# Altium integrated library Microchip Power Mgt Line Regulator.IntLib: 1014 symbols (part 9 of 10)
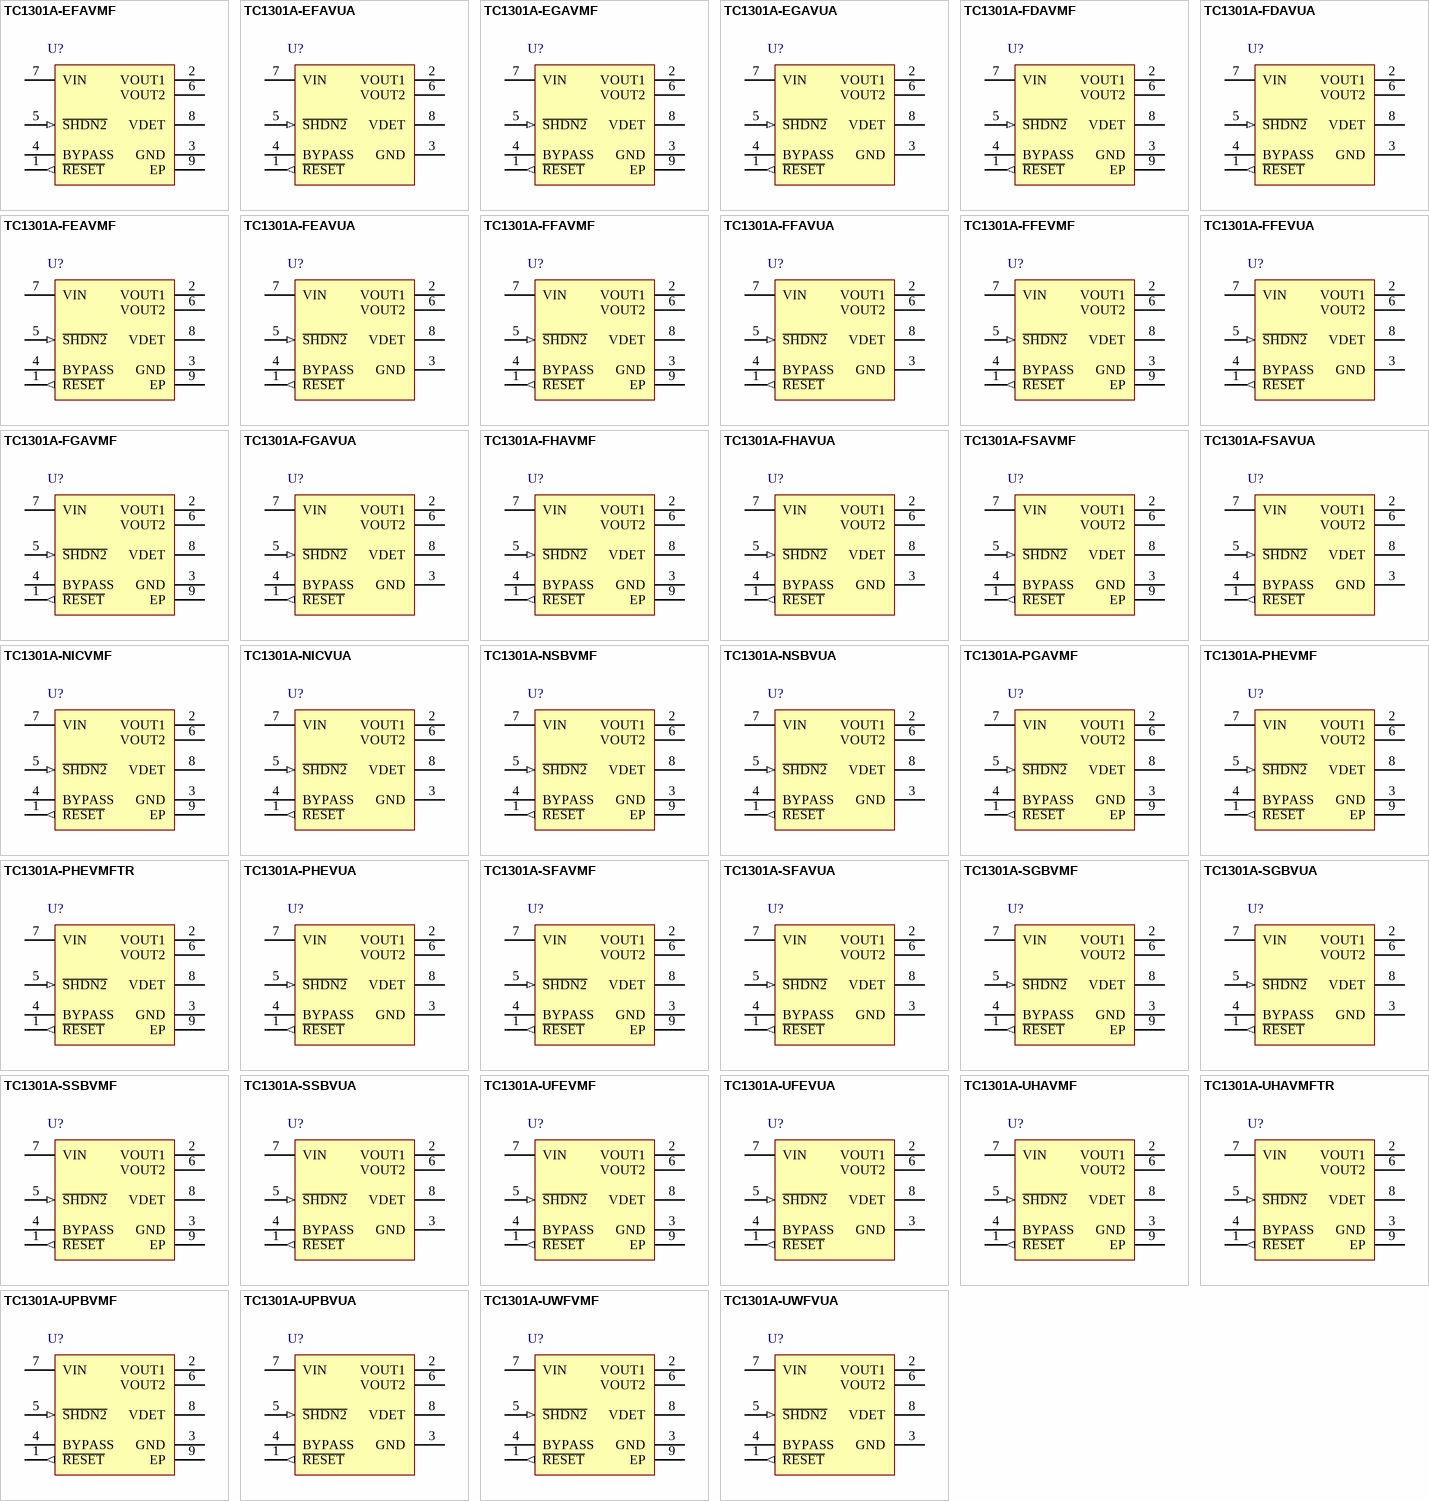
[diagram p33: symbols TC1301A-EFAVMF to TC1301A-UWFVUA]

## TC1301A-UHAVMFTR
designator U?
Dual LDO with Microcontroller Active-Low Reset Function, 8-Pin DFN, Extended Temperature, Tape and Reel
footprint DFN-MF8 (SON, 8-Leads, Body 3x3mm, Pitch 0.65mm, Microchip Recommended)
pins: 1 ~{RESET} (out), 2 VOUT1 (power), 3 GND (power), 4 BYPASS, 5 ~{SHDN2} (in), 6 VOUT2 (power), 7 VIN (power), 8 VDET (power), 9 EP (power)

## TC1301A-UPBVMF
designator U?
Dual LDO with Microcontroller Active-Low Reset Function, 8-Pin DFN, Extended Temperature
footprint DFN-MF8 (SON, 8-Leads, Body 3x3mm, Pitch 0.65mm, Microchip Recommended)
pins: 1 ~{RESET} (out), 2 VOUT1 (power), 3 GND (power), 4 BYPASS, 5 ~{SHDN2} (in), 6 VOUT2 (power), 7 VIN (power), 8 VDET (power), 9 EP (power)

## TC1301A-UPBVUA
designator U?
Dual LDO with Microcontroller Active-Low Reset Function, 8-Pin MSOP, Extended Temperature
footprint MSOP-UA8_N (TSOP, 8-Leads, Body 3x3mm, Pitch 0.65mm, IPC Medium Density)
footprint MSOP-UA8_L (TSOP, 8-Leads, Body 3x3mm, Pitch 0.65mm, IPC High Density)
footprint MSOP-UA8_M (TSOP, 8-Leads, Body 3x3mm, Pitch 0.65mm, IPC Low Density)
pins: 1 ~{RESET} (out), 2 VOUT1 (power), 3 GND (power), 4 BYPASS, 5 ~{SHDN2} (in), 6 VOUT2 (power), 7 VIN (power), 8 VDET (power)

## TC1301A-UWFVMF
designator U?
Dual LDO with Microcontroller Active-Low Reset Function, 8-Pin DFN, Extended Temperature
footprint DFN-MF8 (SON, 8-Leads, Body 3x3mm, Pitch 0.65mm, Microchip Recommended)
pins: 1 ~{RESET} (out), 2 VOUT1 (power), 3 GND (power), 4 BYPASS, 5 ~{SHDN2} (in), 6 VOUT2 (power), 7 VIN (power), 8 VDET (power), 9 EP (power)

## TC1301A-UWFVUA
designator U?
Dual LDO with Microcontroller Active-Low Reset Function, 8-Pin MSOP, Extended Temperature
footprint MSOP-UA8_N (TSOP, 8-Leads, Body 3x3mm, Pitch 0.65mm, IPC Medium Density)
footprint MSOP-UA8_L (TSOP, 8-Leads, Body 3x3mm, Pitch 0.65mm, IPC High Density)
footprint MSOP-UA8_M (TSOP, 8-Leads, Body 3x3mm, Pitch 0.65mm, IPC Low Density)
pins: 1 ~{RESET} (out), 2 VOUT1 (power), 3 GND (power), 4 BYPASS, 5 ~{SHDN2} (in), 6 VOUT2 (power), 7 VIN (power), 8 VDET (power)

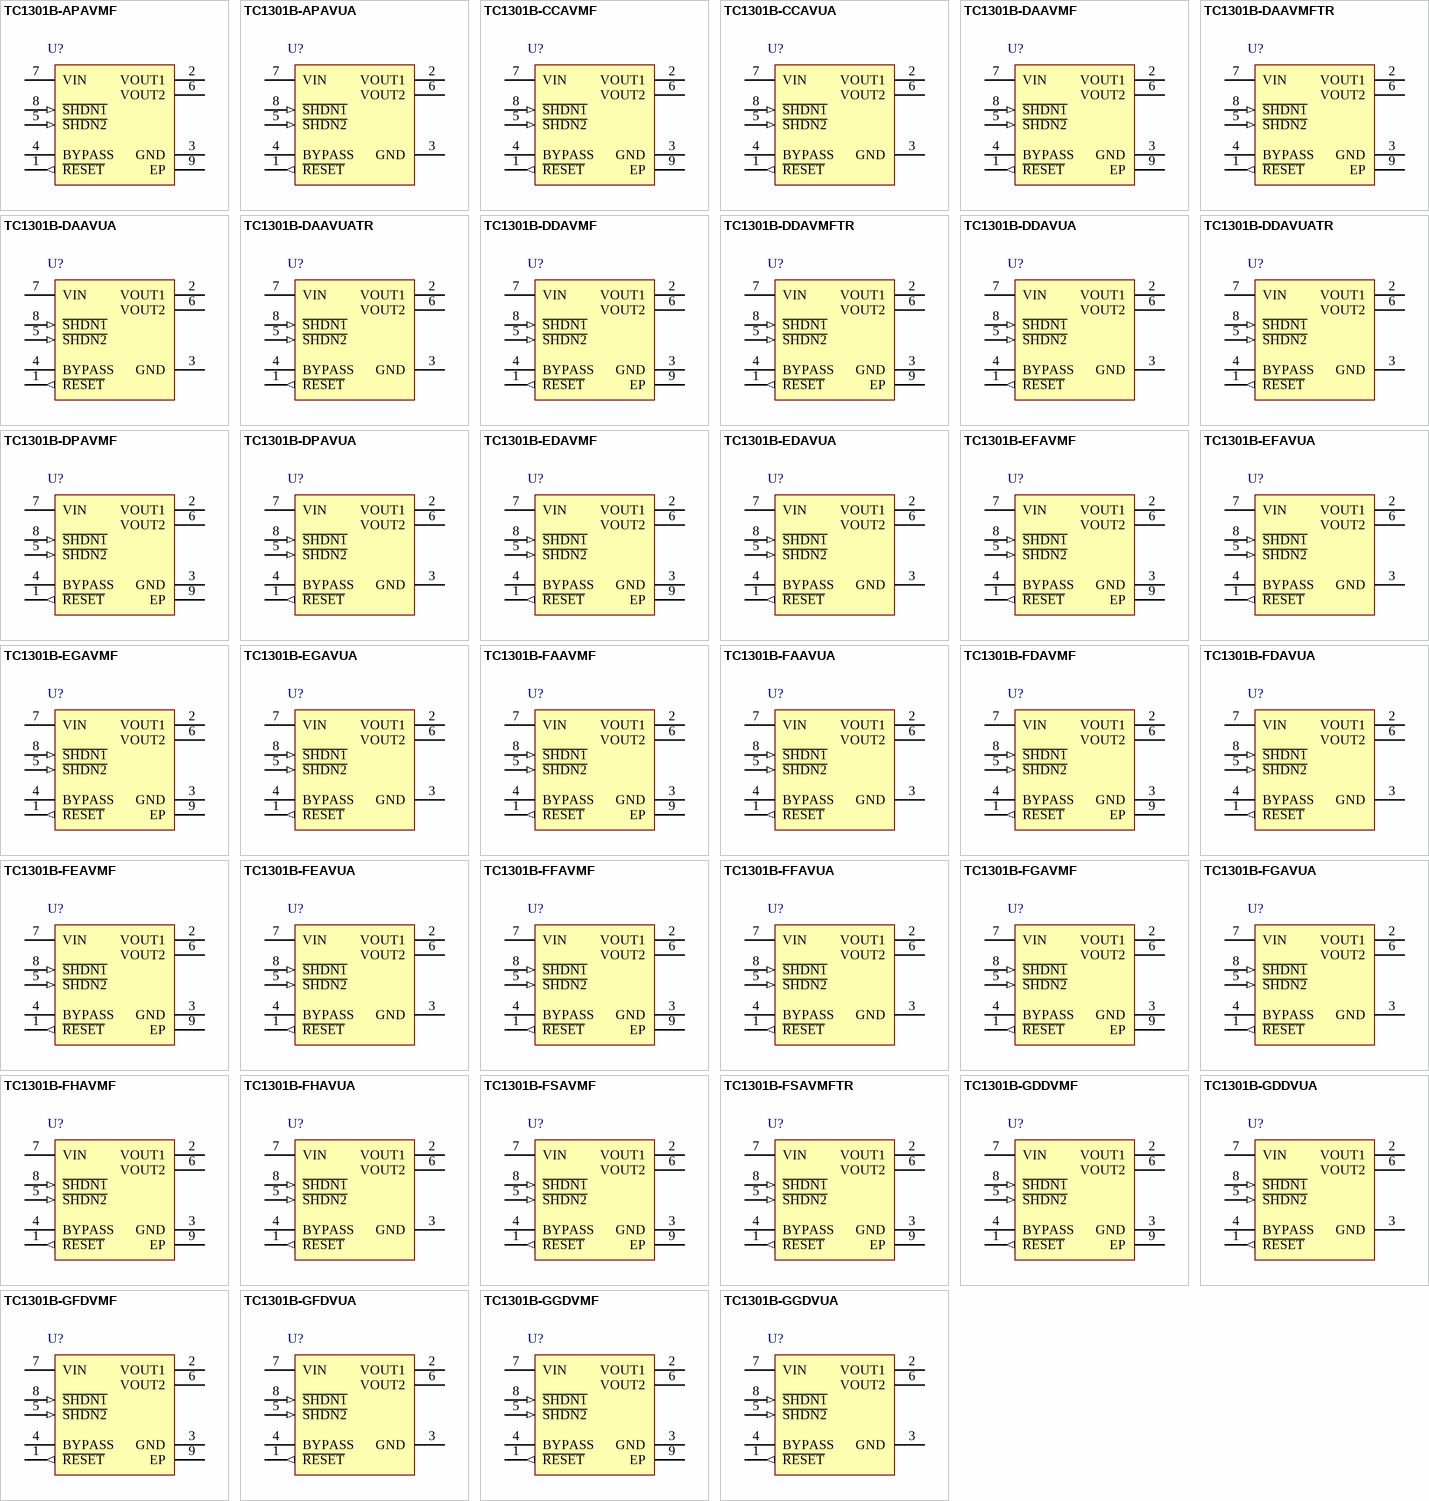
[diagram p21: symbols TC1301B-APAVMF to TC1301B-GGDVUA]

## TC1301B-APAVMF
designator U?
Dual LDO with Microcontroller Active-Low Reset Function, 8-Pin DFN, Extended Temperature
footprint DFN-MF8 (SON, 8-Leads, Body 3x3mm, Pitch 0.65mm, Microchip Recommended)
pins: 1 ~{RESET} (out), 2 VOUT1 (power), 3 GND (power), 4 BYPASS, 5 ~{SHDN2} (in), 6 VOUT2 (power), 7 VIN (power), 8 ~{SHDN1} (in), 9 EP (power)

## TC1301B-APAVUA
designator U?
Dual LDO with Microcontroller Active-Low Reset Function, 8-Pin MSOP, Extended Temperature
footprint MSOP-UA8_N (TSOP, 8-Leads, Body 3x3mm, Pitch 0.65mm, IPC Medium Density)
footprint MSOP-UA8_L (TSOP, 8-Leads, Body 3x3mm, Pitch 0.65mm, IPC High Density)
footprint MSOP-UA8_M (TSOP, 8-Leads, Body 3x3mm, Pitch 0.65mm, IPC Low Density)
pins: 1 ~{RESET} (out), 2 VOUT1 (power), 3 GND (power), 4 BYPASS, 5 ~{SHDN2} (in), 6 VOUT2 (power), 7 VIN (power), 8 ~{SHDN1} (in)

## TC1301B-CCAVMF
designator U?
Dual LDO with Microcontroller Active-Low Reset Function, 8-Pin DFN, Extended Temperature
footprint DFN-MF8 (SON, 8-Leads, Body 3x3mm, Pitch 0.65mm, Microchip Recommended)
pins: 1 ~{RESET} (out), 2 VOUT1 (power), 3 GND (power), 4 BYPASS, 5 ~{SHDN2} (in), 6 VOUT2 (power), 7 VIN (power), 8 ~{SHDN1} (in), 9 EP (power)

## TC1301B-CCAVUA
designator U?
Dual LDO with Microcontroller Active-Low Reset Function, 8-Pin MSOP, Extended Temperature
footprint MSOP-UA8_N (TSOP, 8-Leads, Body 3x3mm, Pitch 0.65mm, IPC Medium Density)
footprint MSOP-UA8_L (TSOP, 8-Leads, Body 3x3mm, Pitch 0.65mm, IPC High Density)
footprint MSOP-UA8_M (TSOP, 8-Leads, Body 3x3mm, Pitch 0.65mm, IPC Low Density)
pins: 1 ~{RESET} (out), 2 VOUT1 (power), 3 GND (power), 4 BYPASS, 5 ~{SHDN2} (in), 6 VOUT2 (power), 7 VIN (power), 8 ~{SHDN1} (in)

## TC1301B-DAAVMF
designator U?
Dual LDO with Microcontroller Active-Low Reset Function, 8-Pin DFN, Extended Temperature
footprint DFN-MF8 (SON, 8-Leads, Body 3x3mm, Pitch 0.65mm, Microchip Recommended)
pins: 1 ~{RESET} (out), 2 VOUT1 (power), 3 GND (power), 4 BYPASS, 5 ~{SHDN2} (in), 6 VOUT2 (power), 7 VIN (power), 8 ~{SHDN1} (in), 9 EP (power)

## TC1301B-DAAVMFTR
designator U?
Dual LDO with Microcontroller Active-Low Reset Function, 8-Pin DFN, Extended Temperature, Tape and Reel
footprint DFN-MF8 (SON, 8-Leads, Body 3x3mm, Pitch 0.65mm, Microchip Recommended)
pins: 1 ~{RESET} (out), 2 VOUT1 (power), 3 GND (power), 4 BYPASS, 5 ~{SHDN2} (in), 6 VOUT2 (power), 7 VIN (power), 8 ~{SHDN1} (in), 9 EP (power)

## TC1301B-DAAVUA
designator U?
Dual LDO with Microcontroller Active-Low Reset Function, 8-Pin MSOP, Extended Temperature
footprint MSOP-UA8_N (TSOP, 8-Leads, Body 3x3mm, Pitch 0.65mm, IPC Medium Density)
footprint MSOP-UA8_L (TSOP, 8-Leads, Body 3x3mm, Pitch 0.65mm, IPC High Density)
footprint MSOP-UA8_M (TSOP, 8-Leads, Body 3x3mm, Pitch 0.65mm, IPC Low Density)
pins: 1 ~{RESET} (out), 2 VOUT1 (power), 3 GND (power), 4 BYPASS, 5 ~{SHDN2} (in), 6 VOUT2 (power), 7 VIN (power), 8 ~{SHDN1} (in)

## TC1301B-DAAVUATR
designator U?
Dual LDO with Microcontroller Active-Low Reset Function, 8-Pin MSOP, Extended Temperature, Tape and Reel
footprint MSOP-UA8_N (TSOP, 8-Leads, Body 3x3mm, Pitch 0.65mm, IPC Medium Density)
footprint MSOP-UA8_L (TSOP, 8-Leads, Body 3x3mm, Pitch 0.65mm, IPC High Density)
footprint MSOP-UA8_M (TSOP, 8-Leads, Body 3x3mm, Pitch 0.65mm, IPC Low Density)
pins: 1 ~{RESET} (out), 2 VOUT1 (power), 3 GND (power), 4 BYPASS, 5 ~{SHDN2} (in), 6 VOUT2 (power), 7 VIN (power), 8 ~{SHDN1} (in)

## TC1301B-DDAVMF
designator U?
Dual LDO with Microcontroller Active-Low Reset Function, 8-Pin DFN, Extended Temperature
footprint DFN-MF8 (SON, 8-Leads, Body 3x3mm, Pitch 0.65mm, Microchip Recommended)
pins: 1 ~{RESET} (out), 2 VOUT1 (power), 3 GND (power), 4 BYPASS, 5 ~{SHDN2} (in), 6 VOUT2 (power), 7 VIN (power), 8 ~{SHDN1} (in), 9 EP (power)

## TC1301B-DDAVMFTR
designator U?
Dual LDO with Microcontroller Active-Low Reset Function, 8-Pin DFN, Extended Temperature, Tape and Reel
footprint DFN-MF8 (SON, 8-Leads, Body 3x3mm, Pitch 0.65mm, Microchip Recommended)
pins: 1 ~{RESET} (out), 2 VOUT1 (power), 3 GND (power), 4 BYPASS, 5 ~{SHDN2} (in), 6 VOUT2 (power), 7 VIN (power), 8 ~{SHDN1} (in), 9 EP (power)

## TC1301B-DDAVUA
designator U?
Dual LDO with Microcontroller Active-Low Reset Function, 8-Pin MSOP, Extended Temperature
footprint MSOP-UA8_N (TSOP, 8-Leads, Body 3x3mm, Pitch 0.65mm, IPC Medium Density)
footprint MSOP-UA8_L (TSOP, 8-Leads, Body 3x3mm, Pitch 0.65mm, IPC High Density)
footprint MSOP-UA8_M (TSOP, 8-Leads, Body 3x3mm, Pitch 0.65mm, IPC Low Density)
pins: 1 ~{RESET} (out), 2 VOUT1 (power), 3 GND (power), 4 BYPASS, 5 ~{SHDN2} (in), 6 VOUT2 (power), 7 VIN (power), 8 ~{SHDN1} (in)

## TC1301B-DDAVUATR
designator U?
Dual LDO with Microcontroller Active-Low Reset Function, 8-Pin MSOP, Extended Temperature, Tape and Reel
footprint MSOP-UA8_N (TSOP, 8-Leads, Body 3x3mm, Pitch 0.65mm, IPC Medium Density)
footprint MSOP-UA8_L (TSOP, 8-Leads, Body 3x3mm, Pitch 0.65mm, IPC High Density)
footprint MSOP-UA8_M (TSOP, 8-Leads, Body 3x3mm, Pitch 0.65mm, IPC Low Density)
pins: 1 ~{RESET} (out), 2 VOUT1 (power), 3 GND (power), 4 BYPASS, 5 ~{SHDN2} (in), 6 VOUT2 (power), 7 VIN (power), 8 ~{SHDN1} (in)

## TC1301B-DPAVMF
designator U?
Dual LDO with Microcontroller Active-Low Reset Function, 8-Pin DFN, Extended Temperature
footprint DFN-MF8 (SON, 8-Leads, Body 3x3mm, Pitch 0.65mm, Microchip Recommended)
pins: 1 ~{RESET} (out), 2 VOUT1 (power), 3 GND (power), 4 BYPASS, 5 ~{SHDN2} (in), 6 VOUT2 (power), 7 VIN (power), 8 ~{SHDN1} (in), 9 EP (power)

## TC1301B-DPAVUA
designator U?
Dual LDO with Microcontroller Active-Low Reset Function, 8-Pin MSOP, Extended Temperature
footprint MSOP-UA8_N (TSOP, 8-Leads, Body 3x3mm, Pitch 0.65mm, IPC Medium Density)
footprint MSOP-UA8_L (TSOP, 8-Leads, Body 3x3mm, Pitch 0.65mm, IPC High Density)
footprint MSOP-UA8_M (TSOP, 8-Leads, Body 3x3mm, Pitch 0.65mm, IPC Low Density)
pins: 1 ~{RESET} (out), 2 VOUT1 (power), 3 GND (power), 4 BYPASS, 5 ~{SHDN2} (in), 6 VOUT2 (power), 7 VIN (power), 8 ~{SHDN1} (in)

## TC1301B-EDAVMF
designator U?
Dual LDO with Microcontroller Active-Low Reset Function, 8-Pin DFN, Extended Temperature
footprint DFN-MF8 (SON, 8-Leads, Body 3x3mm, Pitch 0.65mm, Microchip Recommended)
pins: 1 ~{RESET} (out), 2 VOUT1 (power), 3 GND (power), 4 BYPASS, 5 ~{SHDN2} (in), 6 VOUT2 (power), 7 VIN (power), 8 ~{SHDN1} (in), 9 EP (power)

## TC1301B-EDAVUA
designator U?
Dual LDO with Microcontroller Active-Low Reset Function, 8-Pin MSOP, Extended Temperature
footprint MSOP-UA8_N (TSOP, 8-Leads, Body 3x3mm, Pitch 0.65mm, IPC Medium Density)
footprint MSOP-UA8_L (TSOP, 8-Leads, Body 3x3mm, Pitch 0.65mm, IPC High Density)
footprint MSOP-UA8_M (TSOP, 8-Leads, Body 3x3mm, Pitch 0.65mm, IPC Low Density)
pins: 1 ~{RESET} (out), 2 VOUT1 (power), 3 GND (power), 4 BYPASS, 5 ~{SHDN2} (in), 6 VOUT2 (power), 7 VIN (power), 8 ~{SHDN1} (in)

## TC1301B-EFAVMF
designator U?
Dual LDO with Microcontroller Active-Low Reset Function, 8-Pin DFN, Extended Temperature
footprint DFN-MF8 (SON, 8-Leads, Body 3x3mm, Pitch 0.65mm, Microchip Recommended)
pins: 1 ~{RESET} (out), 2 VOUT1 (power), 3 GND (power), 4 BYPASS, 5 ~{SHDN2} (in), 6 VOUT2 (power), 7 VIN (power), 8 ~{SHDN1} (in), 9 EP (power)

## TC1301B-EFAVUA
designator U?
Dual LDO with Microcontroller Active-Low Reset Function, 8-Pin MSOP, Extended Temperature
footprint MSOP-UA8_N (TSOP, 8-Leads, Body 3x3mm, Pitch 0.65mm, IPC Medium Density)
footprint MSOP-UA8_L (TSOP, 8-Leads, Body 3x3mm, Pitch 0.65mm, IPC High Density)
footprint MSOP-UA8_M (TSOP, 8-Leads, Body 3x3mm, Pitch 0.65mm, IPC Low Density)
pins: 1 ~{RESET} (out), 2 VOUT1 (power), 3 GND (power), 4 BYPASS, 5 ~{SHDN2} (in), 6 VOUT2 (power), 7 VIN (power), 8 ~{SHDN1} (in)

## TC1301B-EGAVMF
designator U?
Dual LDO with Microcontroller Active-Low Reset Function, 8-Pin DFN, Extended Temperature
footprint DFN-MF8 (SON, 8-Leads, Body 3x3mm, Pitch 0.65mm, Microchip Recommended)
pins: 1 ~{RESET} (out), 2 VOUT1 (power), 3 GND (power), 4 BYPASS, 5 ~{SHDN2} (in), 6 VOUT2 (power), 7 VIN (power), 8 ~{SHDN1} (in), 9 EP (power)

## TC1301B-EGAVUA
designator U?
Dual LDO with Microcontroller Active-Low Reset Function, 8-Pin MSOP, Extended Temperature
footprint MSOP-UA8_N (TSOP, 8-Leads, Body 3x3mm, Pitch 0.65mm, IPC Medium Density)
footprint MSOP-UA8_L (TSOP, 8-Leads, Body 3x3mm, Pitch 0.65mm, IPC High Density)
footprint MSOP-UA8_M (TSOP, 8-Leads, Body 3x3mm, Pitch 0.65mm, IPC Low Density)
pins: 1 ~{RESET} (out), 2 VOUT1 (power), 3 GND (power), 4 BYPASS, 5 ~{SHDN2} (in), 6 VOUT2 (power), 7 VIN (power), 8 ~{SHDN1} (in)

## TC1301B-FAAVMF
designator U?
Dual LDO with Microcontroller Active-Low Reset Function, 8-Pin DFN, Extended Temperature
footprint DFN-MF8 (SON, 8-Leads, Body 3x3mm, Pitch 0.65mm, Microchip Recommended)
pins: 1 ~{RESET} (out), 2 VOUT1 (power), 3 GND (power), 4 BYPASS, 5 ~{SHDN2} (in), 6 VOUT2 (power), 7 VIN (power), 8 ~{SHDN1} (in), 9 EP (power)

## TC1301B-FAAVUA
designator U?
Dual LDO with Microcontroller Active-Low Reset Function, 8-Pin MSOP, Extended Temperature
footprint MSOP-UA8_N (TSOP, 8-Leads, Body 3x3mm, Pitch 0.65mm, IPC Medium Density)
footprint MSOP-UA8_L (TSOP, 8-Leads, Body 3x3mm, Pitch 0.65mm, IPC High Density)
footprint MSOP-UA8_M (TSOP, 8-Leads, Body 3x3mm, Pitch 0.65mm, IPC Low Density)
pins: 1 ~{RESET} (out), 2 VOUT1 (power), 3 GND (power), 4 BYPASS, 5 ~{SHDN2} (in), 6 VOUT2 (power), 7 VIN (power), 8 ~{SHDN1} (in)

## TC1301B-FDAVMF
designator U?
Dual LDO with Microcontroller Active-Low Reset Function, 8-Pin DFN, Extended Temperature
footprint DFN-MF8 (SON, 8-Leads, Body 3x3mm, Pitch 0.65mm, Microchip Recommended)
pins: 1 ~{RESET} (out), 2 VOUT1 (power), 3 GND (power), 4 BYPASS, 5 ~{SHDN2} (in), 6 VOUT2 (power), 7 VIN (power), 8 ~{SHDN1} (in), 9 EP (power)

## TC1301B-FDAVUA
designator U?
Dual LDO with Microcontroller Active-Low Reset Function, 8-Pin MSOP, Extended Temperature
footprint MSOP-UA8_N (TSOP, 8-Leads, Body 3x3mm, Pitch 0.65mm, IPC Medium Density)
footprint MSOP-UA8_L (TSOP, 8-Leads, Body 3x3mm, Pitch 0.65mm, IPC High Density)
footprint MSOP-UA8_M (TSOP, 8-Leads, Body 3x3mm, Pitch 0.65mm, IPC Low Density)
pins: 1 ~{RESET} (out), 2 VOUT1 (power), 3 GND (power), 4 BYPASS, 5 ~{SHDN2} (in), 6 VOUT2 (power), 7 VIN (power), 8 ~{SHDN1} (in)

## TC1301B-FEAVMF
designator U?
Dual LDO with Microcontroller Active-Low Reset Function, 8-Pin DFN, Extended Temperature
footprint DFN-MF8 (SON, 8-Leads, Body 3x3mm, Pitch 0.65mm, Microchip Recommended)
pins: 1 ~{RESET} (out), 2 VOUT1 (power), 3 GND (power), 4 BYPASS, 5 ~{SHDN2} (in), 6 VOUT2 (power), 7 VIN (power), 8 ~{SHDN1} (in), 9 EP (power)

## TC1301B-FEAVUA
designator U?
Dual LDO with Microcontroller Active-Low Reset Function, 8-Pin MSOP, Extended Temperature
footprint MSOP-UA8_N (TSOP, 8-Leads, Body 3x3mm, Pitch 0.65mm, IPC Medium Density)
footprint MSOP-UA8_L (TSOP, 8-Leads, Body 3x3mm, Pitch 0.65mm, IPC High Density)
footprint MSOP-UA8_M (TSOP, 8-Leads, Body 3x3mm, Pitch 0.65mm, IPC Low Density)
pins: 1 ~{RESET} (out), 2 VOUT1 (power), 3 GND (power), 4 BYPASS, 5 ~{SHDN2} (in), 6 VOUT2 (power), 7 VIN (power), 8 ~{SHDN1} (in)

## TC1301B-FFAVMF
designator U?
Dual LDO with Microcontroller Active-Low Reset Function, 8-Pin DFN, Extended Temperature
footprint DFN-MF8 (SON, 8-Leads, Body 3x3mm, Pitch 0.65mm, Microchip Recommended)
pins: 1 ~{RESET} (out), 2 VOUT1 (power), 3 GND (power), 4 BYPASS, 5 ~{SHDN2} (in), 6 VOUT2 (power), 7 VIN (power), 8 ~{SHDN1} (in), 9 EP (power)

## TC1301B-FFAVUA
designator U?
Dual LDO with Microcontroller Active-Low Reset Function, 8-Pin MSOP, Extended Temperature
footprint MSOP-UA8_N (TSOP, 8-Leads, Body 3x3mm, Pitch 0.65mm, IPC Medium Density)
footprint MSOP-UA8_L (TSOP, 8-Leads, Body 3x3mm, Pitch 0.65mm, IPC High Density)
footprint MSOP-UA8_M (TSOP, 8-Leads, Body 3x3mm, Pitch 0.65mm, IPC Low Density)
pins: 1 ~{RESET} (out), 2 VOUT1 (power), 3 GND (power), 4 BYPASS, 5 ~{SHDN2} (in), 6 VOUT2 (power), 7 VIN (power), 8 ~{SHDN1} (in)

## TC1301B-FGAVMF
designator U?
Dual LDO with Microcontroller Active-Low Reset Function, 8-Pin DFN, Extended Temperature
footprint DFN-MF8 (SON, 8-Leads, Body 3x3mm, Pitch 0.65mm, Microchip Recommended)
pins: 1 ~{RESET} (out), 2 VOUT1 (power), 3 GND (power), 4 BYPASS, 5 ~{SHDN2} (in), 6 VOUT2 (power), 7 VIN (power), 8 ~{SHDN1} (in), 9 EP (power)

## TC1301B-FGAVUA
designator U?
Dual LDO with Microcontroller Active-Low Reset Function, 8-Pin MSOP, Extended Temperature
footprint MSOP-UA8_N (TSOP, 8-Leads, Body 3x3mm, Pitch 0.65mm, IPC Medium Density)
footprint MSOP-UA8_L (TSOP, 8-Leads, Body 3x3mm, Pitch 0.65mm, IPC High Density)
footprint MSOP-UA8_M (TSOP, 8-Leads, Body 3x3mm, Pitch 0.65mm, IPC Low Density)
pins: 1 ~{RESET} (out), 2 VOUT1 (power), 3 GND (power), 4 BYPASS, 5 ~{SHDN2} (in), 6 VOUT2 (power), 7 VIN (power), 8 ~{SHDN1} (in)

## TC1301B-FHAVMF
designator U?
Dual LDO with Microcontroller Active-Low Reset Function, 8-Pin DFN, Extended Temperature
footprint DFN-MF8 (SON, 8-Leads, Body 3x3mm, Pitch 0.65mm, Microchip Recommended)
pins: 1 ~{RESET} (out), 2 VOUT1 (power), 3 GND (power), 4 BYPASS, 5 ~{SHDN2} (in), 6 VOUT2 (power), 7 VIN (power), 8 ~{SHDN1} (in), 9 EP (power)

## TC1301B-FHAVUA
designator U?
Dual LDO with Microcontroller Active-Low Reset Function, 8-Pin MSOP, Extended Temperature
footprint MSOP-UA8_N (TSOP, 8-Leads, Body 3x3mm, Pitch 0.65mm, IPC Medium Density)
footprint MSOP-UA8_L (TSOP, 8-Leads, Body 3x3mm, Pitch 0.65mm, IPC High Density)
footprint MSOP-UA8_M (TSOP, 8-Leads, Body 3x3mm, Pitch 0.65mm, IPC Low Density)
pins: 1 ~{RESET} (out), 2 VOUT1 (power), 3 GND (power), 4 BYPASS, 5 ~{SHDN2} (in), 6 VOUT2 (power), 7 VIN (power), 8 ~{SHDN1} (in)

## TC1301B-FSAVMF
designator U?
Dual LDO with Microcontroller Active-Low Reset Function, 8-Pin DFN, Extended Temperature
footprint DFN-MF8 (SON, 8-Leads, Body 3x3mm, Pitch 0.65mm, Microchip Recommended)
pins: 1 ~{RESET} (out), 2 VOUT1 (power), 3 GND (power), 4 BYPASS, 5 ~{SHDN2} (in), 6 VOUT2 (power), 7 VIN (power), 8 ~{SHDN1} (in), 9 EP (power)

## TC1301B-FSAVMFTR
designator U?
Dual LDO with Microcontroller Active-Low Reset Function, 8-Pin DFN, Extended Temperature, Tape and Reel
footprint DFN-MF8 (SON, 8-Leads, Body 3x3mm, Pitch 0.65mm, Microchip Recommended)
pins: 1 ~{RESET} (out), 2 VOUT1 (power), 3 GND (power), 4 BYPASS, 5 ~{SHDN2} (in), 6 VOUT2 (power), 7 VIN (power), 8 ~{SHDN1} (in), 9 EP (power)

## TC1301B-GDDVMF
designator U?
Dual LDO with Microcontroller Active-Low Reset Function, 8-Pin DFN, Extended Temperature
footprint DFN-MF8 (SON, 8-Leads, Body 3x3mm, Pitch 0.65mm, Microchip Recommended)
pins: 1 ~{RESET} (out), 2 VOUT1 (power), 3 GND (power), 4 BYPASS, 5 ~{SHDN2} (in), 6 VOUT2 (power), 7 VIN (power), 8 ~{SHDN1} (in), 9 EP (power)

## TC1301B-GDDVUA
designator U?
Dual LDO with Microcontroller Active-Low Reset Function, 8-Pin MSOP, Extended Temperature
footprint MSOP-UA8_N (TSOP, 8-Leads, Body 3x3mm, Pitch 0.65mm, IPC Medium Density)
footprint MSOP-UA8_L (TSOP, 8-Leads, Body 3x3mm, Pitch 0.65mm, IPC High Density)
footprint MSOP-UA8_M (TSOP, 8-Leads, Body 3x3mm, Pitch 0.65mm, IPC Low Density)
pins: 1 ~{RESET} (out), 2 VOUT1 (power), 3 GND (power), 4 BYPASS, 5 ~{SHDN2} (in), 6 VOUT2 (power), 7 VIN (power), 8 ~{SHDN1} (in)

## TC1301B-GFDVMF
designator U?
Dual LDO with Microcontroller Active-Low Reset Function, 8-Pin DFN, Extended Temperature
footprint DFN-MF8 (SON, 8-Leads, Body 3x3mm, Pitch 0.65mm, Microchip Recommended)
pins: 1 ~{RESET} (out), 2 VOUT1 (power), 3 GND (power), 4 BYPASS, 5 ~{SHDN2} (in), 6 VOUT2 (power), 7 VIN (power), 8 ~{SHDN1} (in), 9 EP (power)

## TC1301B-GFDVUA
designator U?
Dual LDO with Microcontroller Active-Low Reset Function, 8-Pin MSOP, Extended Temperature
footprint MSOP-UA8_N (TSOP, 8-Leads, Body 3x3mm, Pitch 0.65mm, IPC Medium Density)
footprint MSOP-UA8_L (TSOP, 8-Leads, Body 3x3mm, Pitch 0.65mm, IPC High Density)
footprint MSOP-UA8_M (TSOP, 8-Leads, Body 3x3mm, Pitch 0.65mm, IPC Low Density)
pins: 1 ~{RESET} (out), 2 VOUT1 (power), 3 GND (power), 4 BYPASS, 5 ~{SHDN2} (in), 6 VOUT2 (power), 7 VIN (power), 8 ~{SHDN1} (in)

## TC1301B-GGDVMF
designator U?
Dual LDO with Microcontroller Active-Low Reset Function, 8-Pin DFN, Extended Temperature
footprint DFN-MF8 (SON, 8-Leads, Body 3x3mm, Pitch 0.65mm, Microchip Recommended)
pins: 1 ~{RESET} (out), 2 VOUT1 (power), 3 GND (power), 4 BYPASS, 5 ~{SHDN2} (in), 6 VOUT2 (power), 7 VIN (power), 8 ~{SHDN1} (in), 9 EP (power)

## TC1301B-GGDVUA
designator U?
Dual LDO with Microcontroller Active-Low Reset Function, 8-Pin MSOP, Extended Temperature
footprint MSOP-UA8_N (TSOP, 8-Leads, Body 3x3mm, Pitch 0.65mm, IPC Medium Density)
footprint MSOP-UA8_L (TSOP, 8-Leads, Body 3x3mm, Pitch 0.65mm, IPC High Density)
footprint MSOP-UA8_M (TSOP, 8-Leads, Body 3x3mm, Pitch 0.65mm, IPC Low Density)
pins: 1 ~{RESET} (out), 2 VOUT1 (power), 3 GND (power), 4 BYPASS, 5 ~{SHDN2} (in), 6 VOUT2 (power), 7 VIN (power), 8 ~{SHDN1} (in)

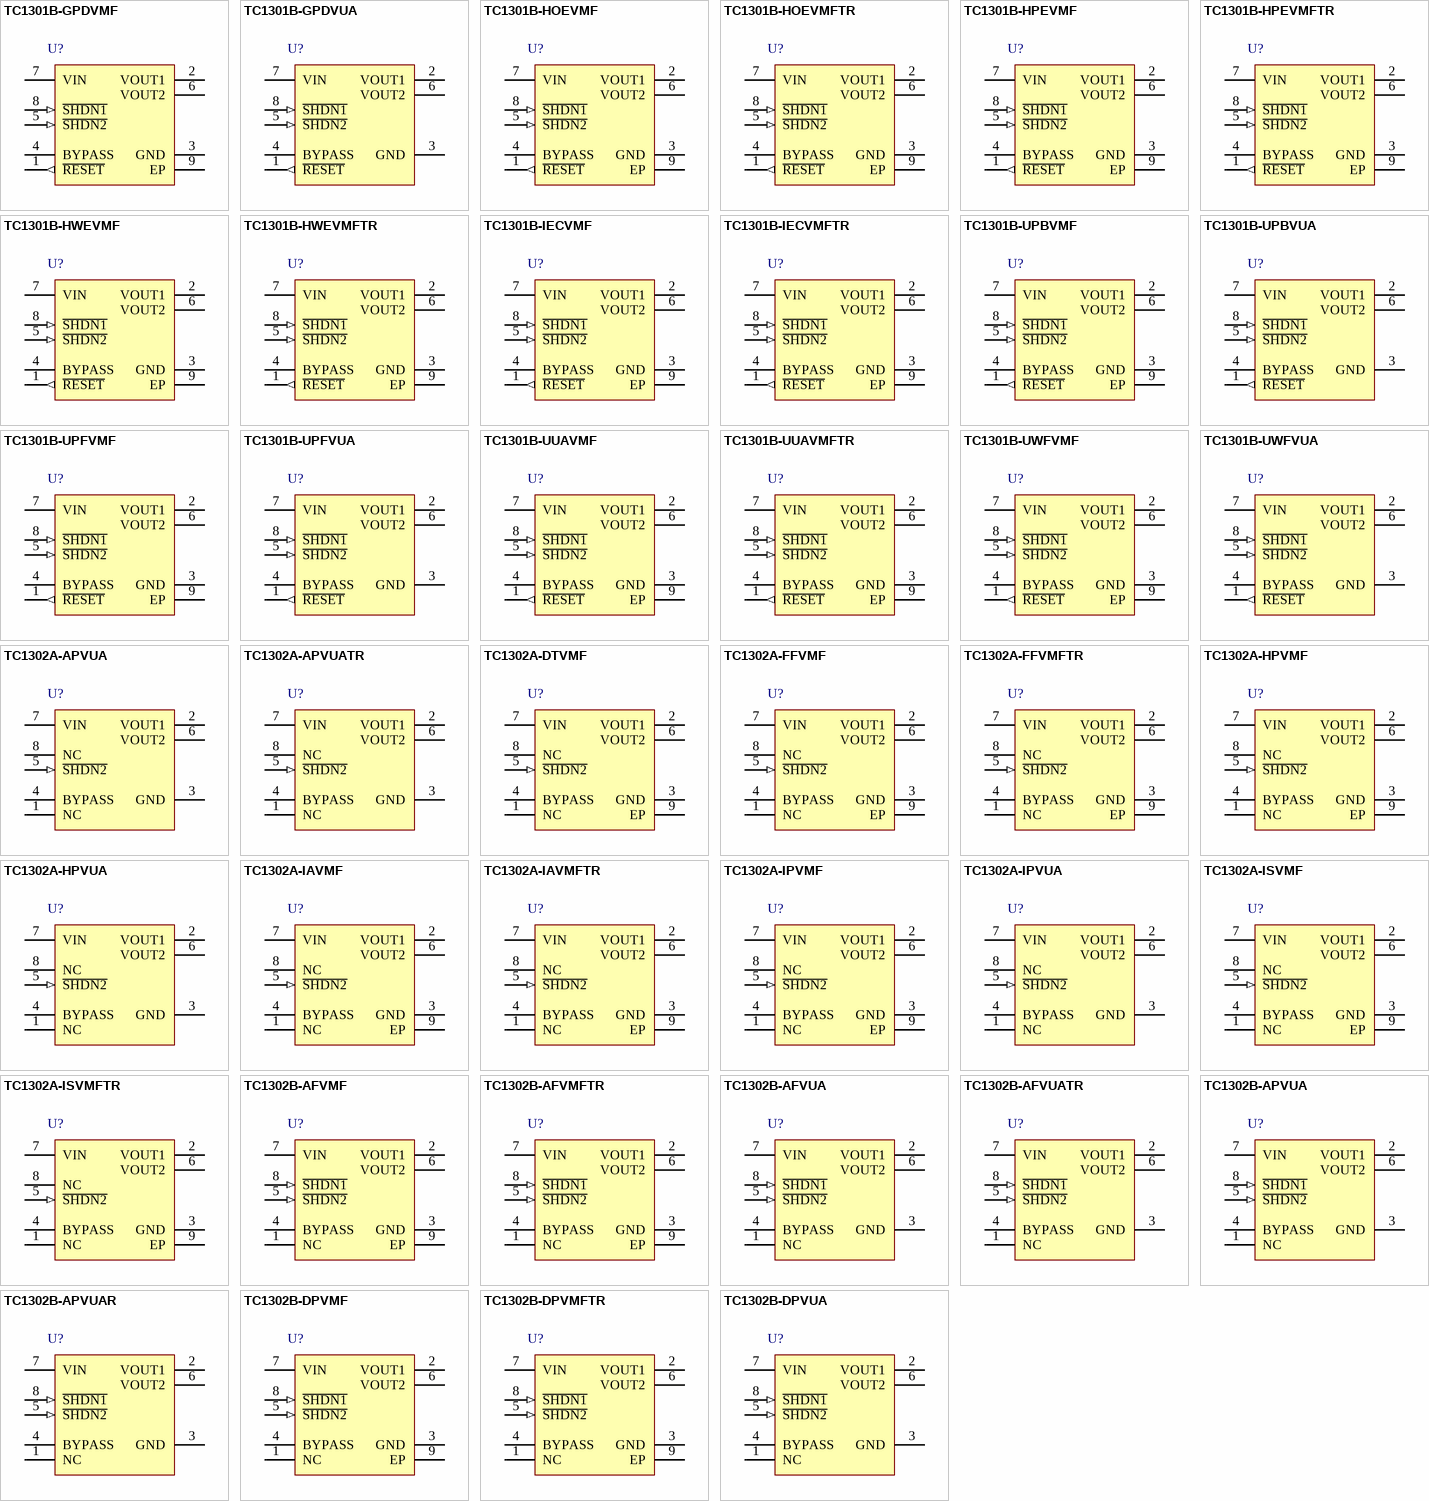
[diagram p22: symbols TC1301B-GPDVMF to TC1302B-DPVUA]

## TC1301B-GPDVMF
designator U?
Dual LDO with Microcontroller Active-Low Reset Function, 8-Pin DFN, Extended Temperature
footprint DFN-MF8 (SON, 8-Leads, Body 3x3mm, Pitch 0.65mm, Microchip Recommended)
pins: 1 ~{RESET} (out), 2 VOUT1 (power), 3 GND (power), 4 BYPASS, 5 ~{SHDN2} (in), 6 VOUT2 (power), 7 VIN (power), 8 ~{SHDN1} (in), 9 EP (power)

## TC1301B-GPDVUA
designator U?
Dual LDO with Microcontroller Active-Low Reset Function, 8-Pin MSOP, Extended Temperature
footprint MSOP-UA8_N (TSOP, 8-Leads, Body 3x3mm, Pitch 0.65mm, IPC Medium Density)
footprint MSOP-UA8_L (TSOP, 8-Leads, Body 3x3mm, Pitch 0.65mm, IPC High Density)
footprint MSOP-UA8_M (TSOP, 8-Leads, Body 3x3mm, Pitch 0.65mm, IPC Low Density)
pins: 1 ~{RESET} (out), 2 VOUT1 (power), 3 GND (power), 4 BYPASS, 5 ~{SHDN2} (in), 6 VOUT2 (power), 7 VIN (power), 8 ~{SHDN1} (in)

## TC1301B-HOEVMF
designator U?
Dual LDO with Microcontroller Active-Low Reset Function, 8-Pin DFN, Extended Temperature
footprint DFN-MF8 (SON, 8-Leads, Body 3x3mm, Pitch 0.65mm, Microchip Recommended)
pins: 1 ~{RESET} (out), 2 VOUT1 (power), 3 GND (power), 4 BYPASS, 5 ~{SHDN2} (in), 6 VOUT2 (power), 7 VIN (power), 8 ~{SHDN1} (in), 9 EP (power)

## TC1301B-HOEVMFTR
designator U?
Dual LDO with Microcontroller Active-Low Reset Function, 8-Pin DFN, Extended Temperature, Tape and Reel
footprint DFN-MF8 (SON, 8-Leads, Body 3x3mm, Pitch 0.65mm, Microchip Recommended)
pins: 1 ~{RESET} (out), 2 VOUT1 (power), 3 GND (power), 4 BYPASS, 5 ~{SHDN2} (in), 6 VOUT2 (power), 7 VIN (power), 8 ~{SHDN1} (in), 9 EP (power)

## TC1301B-HPEVMF
designator U?
Dual LDO with Microcontroller Active-Low Reset Function, 8-Pin DFN, Extended Temperature
footprint DFN-MF8 (SON, 8-Leads, Body 3x3mm, Pitch 0.65mm, Microchip Recommended)
pins: 1 ~{RESET} (out), 2 VOUT1 (power), 3 GND (power), 4 BYPASS, 5 ~{SHDN2} (in), 6 VOUT2 (power), 7 VIN (power), 8 ~{SHDN1} (in), 9 EP (power)

## TC1301B-HPEVMFTR
designator U?
Dual LDO with Microcontroller Active-Low Reset Function, 8-Pin DFN, Extended Temperature, Tape and Reel
footprint DFN-MF8 (SON, 8-Leads, Body 3x3mm, Pitch 0.65mm, Microchip Recommended)
pins: 1 ~{RESET} (out), 2 VOUT1 (power), 3 GND (power), 4 BYPASS, 5 ~{SHDN2} (in), 6 VOUT2 (power), 7 VIN (power), 8 ~{SHDN1} (in), 9 EP (power)

## TC1301B-HWEVMF
designator U?
Dual LDO with Microcontroller Active-Low Reset Function, 8-Pin DFN, Extended Temperature
footprint DFN-MF8 (SON, 8-Leads, Body 3x3mm, Pitch 0.65mm, Microchip Recommended)
pins: 1 ~{RESET} (out), 2 VOUT1 (power), 3 GND (power), 4 BYPASS, 5 ~{SHDN2} (in), 6 VOUT2 (power), 7 VIN (power), 8 ~{SHDN1} (in), 9 EP (power)

## TC1301B-HWEVMFTR
designator U?
Dual LDO with Microcontroller Active-Low Reset Function, 8-Pin DFN, Extended Temperature, Tape and Reel
footprint DFN-MF8 (SON, 8-Leads, Body 3x3mm, Pitch 0.65mm, Microchip Recommended)
pins: 1 ~{RESET} (out), 2 VOUT1 (power), 3 GND (power), 4 BYPASS, 5 ~{SHDN2} (in), 6 VOUT2 (power), 7 VIN (power), 8 ~{SHDN1} (in), 9 EP (power)

## TC1301B-IECVMF
designator U?
Dual LDO with Microcontroller Active-Low Reset Function, 8-Pin DFN, Extended Temperature
footprint DFN-MF8 (SON, 8-Leads, Body 3x3mm, Pitch 0.65mm, Microchip Recommended)
pins: 1 ~{RESET} (out), 2 VOUT1 (power), 3 GND (power), 4 BYPASS, 5 ~{SHDN2} (in), 6 VOUT2 (power), 7 VIN (power), 8 ~{SHDN1} (in), 9 EP (power)

## TC1301B-IECVMFTR
designator U?
Dual LDO with Microcontroller Active-Low Reset Function, 8-Pin DFN, Extended Temperature, Tape and Reel
footprint DFN-MF8 (SON, 8-Leads, Body 3x3mm, Pitch 0.65mm, Microchip Recommended)
pins: 1 ~{RESET} (out), 2 VOUT1 (power), 3 GND (power), 4 BYPASS, 5 ~{SHDN2} (in), 6 VOUT2 (power), 7 VIN (power), 8 ~{SHDN1} (in), 9 EP (power)

## TC1301B-UPBVMF
designator U?
Dual LDO with Microcontroller Active-Low Reset Function, 8-Pin DFN, Extended Temperature
footprint DFN-MF8 (SON, 8-Leads, Body 3x3mm, Pitch 0.65mm, Microchip Recommended)
pins: 1 ~{RESET} (out), 2 VOUT1 (power), 3 GND (power), 4 BYPASS, 5 ~{SHDN2} (in), 6 VOUT2 (power), 7 VIN (power), 8 ~{SHDN1} (in), 9 EP (power)

## TC1301B-UPBVUA
designator U?
Dual LDO with Microcontroller Active-Low Reset Function, 8-Pin MSOP, Extended Temperature
footprint MSOP-UA8_N (TSOP, 8-Leads, Body 3x3mm, Pitch 0.65mm, IPC Medium Density)
footprint MSOP-UA8_L (TSOP, 8-Leads, Body 3x3mm, Pitch 0.65mm, IPC High Density)
footprint MSOP-UA8_M (TSOP, 8-Leads, Body 3x3mm, Pitch 0.65mm, IPC Low Density)
pins: 1 ~{RESET} (out), 2 VOUT1 (power), 3 GND (power), 4 BYPASS, 5 ~{SHDN2} (in), 6 VOUT2 (power), 7 VIN (power), 8 ~{SHDN1} (in)

## TC1301B-UPFVMF
designator U?
Dual LDO with Microcontroller Active-Low Reset Function, 8-Pin DFN, Extended Temperature
footprint DFN-MF8 (SON, 8-Leads, Body 3x3mm, Pitch 0.65mm, Microchip Recommended)
pins: 1 ~{RESET} (out), 2 VOUT1 (power), 3 GND (power), 4 BYPASS, 5 ~{SHDN2} (in), 6 VOUT2 (power), 7 VIN (power), 8 ~{SHDN1} (in), 9 EP (power)

## TC1301B-UPFVUA
designator U?
Dual LDO with Microcontroller Active-Low Reset Function, 8-Pin MSOP, Extended Temperature
footprint MSOP-UA8_N (TSOP, 8-Leads, Body 3x3mm, Pitch 0.65mm, IPC Medium Density)
footprint MSOP-UA8_L (TSOP, 8-Leads, Body 3x3mm, Pitch 0.65mm, IPC High Density)
footprint MSOP-UA8_M (TSOP, 8-Leads, Body 3x3mm, Pitch 0.65mm, IPC Low Density)
pins: 1 ~{RESET} (out), 2 VOUT1 (power), 3 GND (power), 4 BYPASS, 5 ~{SHDN2} (in), 6 VOUT2 (power), 7 VIN (power), 8 ~{SHDN1} (in)

## TC1301B-UUAVMF
designator U?
Dual LDO with Microcontroller Active-Low Reset Function, 8-Pin DFN, Extended Temperature
footprint DFN-MF8 (SON, 8-Leads, Body 3x3mm, Pitch 0.65mm, Microchip Recommended)
pins: 1 ~{RESET} (out), 2 VOUT1 (power), 3 GND (power), 4 BYPASS, 5 ~{SHDN2} (in), 6 VOUT2 (power), 7 VIN (power), 8 ~{SHDN1} (in), 9 EP (power)

## TC1301B-UUAVMFTR
designator U?
Dual LDO with Microcontroller Active-Low Reset Function, 8-Pin DFN, Extended Temperature, Tape and Reel
footprint DFN-MF8 (SON, 8-Leads, Body 3x3mm, Pitch 0.65mm, Microchip Recommended)
pins: 1 ~{RESET} (out), 2 VOUT1 (power), 3 GND (power), 4 BYPASS, 5 ~{SHDN2} (in), 6 VOUT2 (power), 7 VIN (power), 8 ~{SHDN1} (in), 9 EP (power)

## TC1301B-UWFVMF
designator U?
Dual LDO with Microcontroller Active-Low Reset Function, 8-Pin DFN, Extended Temperature
footprint DFN-MF8 (SON, 8-Leads, Body 3x3mm, Pitch 0.65mm, Microchip Recommended)
pins: 1 ~{RESET} (out), 2 VOUT1 (power), 3 GND (power), 4 BYPASS, 5 ~{SHDN2} (in), 6 VOUT2 (power), 7 VIN (power), 8 ~{SHDN1} (in), 9 EP (power)

## TC1301B-UWFVUA
designator U?
Dual LDO with Microcontroller Active-Low Reset Function, 8-Pin MSOP, Extended Temperature
footprint MSOP-UA8_N (TSOP, 8-Leads, Body 3x3mm, Pitch 0.65mm, IPC Medium Density)
footprint MSOP-UA8_L (TSOP, 8-Leads, Body 3x3mm, Pitch 0.65mm, IPC High Density)
footprint MSOP-UA8_M (TSOP, 8-Leads, Body 3x3mm, Pitch 0.65mm, IPC Low Density)
pins: 1 ~{RESET} (out), 2 VOUT1 (power), 3 GND (power), 4 BYPASS, 5 ~{SHDN2} (in), 6 VOUT2 (power), 7 VIN (power), 8 ~{SHDN1} (in)

## TC1302A-APVUA
designator U?
Low Quiescent Current Dual Output LDO, 8-Pin MSOP, Extended Temperature
footprint MSOP-UA8_N (TSOP, 8-Leads, Body 3x3mm, Pitch 0.65mm, IPC Medium Density)
footprint MSOP-UA8_L (TSOP, 8-Leads, Body 3x3mm, Pitch 0.65mm, IPC High Density)
footprint MSOP-UA8_M (TSOP, 8-Leads, Body 3x3mm, Pitch 0.65mm, IPC Low Density)
pins: 1 NC, 2 VOUT1 (power), 3 GND (power), 4 BYPASS, 5 ~{SHDN2} (in), 6 VOUT2 (power), 7 VIN (power), 8 NC

## TC1302A-APVUATR
designator U?
Low Quiescent Current Dual Output LDO, 8-Pin MSOP, Extended Temperature, Tape and Reel
footprint MSOP-UA8_N (TSOP, 8-Leads, Body 3x3mm, Pitch 0.65mm, IPC Medium Density)
footprint MSOP-UA8_L (TSOP, 8-Leads, Body 3x3mm, Pitch 0.65mm, IPC High Density)
footprint MSOP-UA8_M (TSOP, 8-Leads, Body 3x3mm, Pitch 0.65mm, IPC Low Density)
pins: 1 NC, 2 VOUT1 (power), 3 GND (power), 4 BYPASS, 5 ~{SHDN2} (in), 6 VOUT2 (power), 7 VIN (power), 8 NC

## TC1302A-DTVMF
designator U?
Low Quiescent Current Dual Output LDO, 8-Pin DFN, Extended Temperature
footprint DFN-MF8 (SON, 8-Leads, Body 3x3mm, Pitch 0.65mm, Microchip Recommended)
pins: 1 NC, 2 VOUT1 (power), 3 GND (power), 4 BYPASS, 5 ~{SHDN2} (in), 6 VOUT2 (power), 7 VIN (power), 8 NC, 9 EP (power)

## TC1302A-FFVMF
designator U?
Low Quiescent Current Dual Output LDO, 8-Pin DFN, Extended Temperature
footprint DFN-MF8 (SON, 8-Leads, Body 3x3mm, Pitch 0.65mm, Microchip Recommended)
pins: 1 NC, 2 VOUT1 (power), 3 GND (power), 4 BYPASS, 5 ~{SHDN2} (in), 6 VOUT2 (power), 7 VIN (power), 8 NC, 9 EP (power)

## TC1302A-FFVMFTR
designator U?
Low Quiescent Current Dual Output LDO, 8-Pin DFN, Extended Temperature, Tape and Reel
footprint DFN-MF8 (SON, 8-Leads, Body 3x3mm, Pitch 0.65mm, Microchip Recommended)
pins: 1 NC, 2 VOUT1 (power), 3 GND (power), 4 BYPASS, 5 ~{SHDN2} (in), 6 VOUT2 (power), 7 VIN (power), 8 NC, 9 EP (power)

## TC1302A-HPVMF
designator U?
Low Quiescent Current Dual Output LDO, 8-Pin DFN, Extended Temperature
footprint DFN-MF8 (SON, 8-Leads, Body 3x3mm, Pitch 0.65mm, Microchip Recommended)
pins: 1 NC, 2 VOUT1 (power), 3 GND (power), 4 BYPASS, 5 ~{SHDN2} (in), 6 VOUT2 (power), 7 VIN (power), 8 NC, 9 EP (power)

## TC1302A-HPVUA
designator U?
Low Quiescent Current Dual Output LDO, 8-Pin MSOP, Extended Temperature
footprint MSOP-UA8_N (TSOP, 8-Leads, Body 3x3mm, Pitch 0.65mm, IPC Medium Density)
footprint MSOP-UA8_L (TSOP, 8-Leads, Body 3x3mm, Pitch 0.65mm, IPC High Density)
footprint MSOP-UA8_M (TSOP, 8-Leads, Body 3x3mm, Pitch 0.65mm, IPC Low Density)
pins: 1 NC, 2 VOUT1 (power), 3 GND (power), 4 BYPASS, 5 ~{SHDN2} (in), 6 VOUT2 (power), 7 VIN (power), 8 NC

## TC1302A-IAVMF
designator U?
Low Quiescent Current Dual Output LDO, 8-Pin DFN, Extended Temperature
footprint DFN-MF8 (SON, 8-Leads, Body 3x3mm, Pitch 0.65mm, Microchip Recommended)
pins: 1 NC, 2 VOUT1 (power), 3 GND (power), 4 BYPASS, 5 ~{SHDN2} (in), 6 VOUT2 (power), 7 VIN (power), 8 NC, 9 EP (power)

## TC1302A-IAVMFTR
designator U?
Low Quiescent Current Dual Output LDO, 8-Pin DFN, Extended Temperature, Tape and Reel
footprint DFN-MF8 (SON, 8-Leads, Body 3x3mm, Pitch 0.65mm, Microchip Recommended)
pins: 1 NC, 2 VOUT1 (power), 3 GND (power), 4 BYPASS, 5 ~{SHDN2} (in), 6 VOUT2 (power), 7 VIN (power), 8 NC, 9 EP (power)

## TC1302A-IPVMF
designator U?
Low Quiescent Current Dual Output LDO, 8-Pin DFN, Extended Temperature
footprint DFN-MF8 (SON, 8-Leads, Body 3x3mm, Pitch 0.65mm, Microchip Recommended)
pins: 1 NC, 2 VOUT1 (power), 3 GND (power), 4 BYPASS, 5 ~{SHDN2} (in), 6 VOUT2 (power), 7 VIN (power), 8 NC, 9 EP (power)

## TC1302A-IPVUA
designator U?
Low Quiescent Current Dual Output LDO, 8-Pin MSOP, Extended Temperature
footprint MSOP-UA8_N (TSOP, 8-Leads, Body 3x3mm, Pitch 0.65mm, IPC Medium Density)
footprint MSOP-UA8_L (TSOP, 8-Leads, Body 3x3mm, Pitch 0.65mm, IPC High Density)
footprint MSOP-UA8_M (TSOP, 8-Leads, Body 3x3mm, Pitch 0.65mm, IPC Low Density)
pins: 1 NC, 2 VOUT1 (power), 3 GND (power), 4 BYPASS, 5 ~{SHDN2} (in), 6 VOUT2 (power), 7 VIN (power), 8 NC

## TC1302A-ISVMF
designator U?
Low Quiescent Current Dual Output LDO, 8-Pin DFN, Industrial Temperature
footprint DFN-MF8 (SON, 8-Leads, Body 3x3mm, Pitch 0.65mm, Microchip Recommended)
pins: 1 NC, 2 VOUT1 (power), 3 GND (power), 4 BYPASS, 5 ~{SHDN2} (in), 6 VOUT2 (power), 7 VIN (power), 8 NC, 9 EP (power)

## TC1302A-ISVMFTR
designator U?
Low Quiescent Current Dual Output LDO, 8-Pin DFN, Extended Temperature, Tape and Reel
footprint DFN-MF8 (SON, 8-Leads, Body 3x3mm, Pitch 0.65mm, Microchip Recommended)
pins: 1 NC, 2 VOUT1 (power), 3 GND (power), 4 BYPASS, 5 ~{SHDN2} (in), 6 VOUT2 (power), 7 VIN (power), 8 NC, 9 EP (power)

## TC1302B-AFVMF
designator U?
Low Quiescent Current Dual Output LDO, 8-Pin DFN, Extended Temperature
footprint DFN-MF8 (SON, 8-Leads, Body 3x3mm, Pitch 0.65mm, Microchip Recommended)
pins: 1 NC, 2 VOUT1 (power), 3 GND (power), 4 BYPASS, 5 ~{SHDN2} (in), 6 VOUT2 (power), 7 VIN (power), 8 ~{SHDN1} (in), 9 EP (power)

## TC1302B-AFVMFTR
designator U?
Low Quiescent Current Dual Output LDO, 8-Pin DFN, Extended Temperature, Tape and Reel
footprint DFN-MF8 (SON, 8-Leads, Body 3x3mm, Pitch 0.65mm, Microchip Recommended)
pins: 1 NC, 2 VOUT1 (power), 3 GND (power), 4 BYPASS, 5 ~{SHDN2} (in), 6 VOUT2 (power), 7 VIN (power), 8 ~{SHDN1} (in), 9 EP (power)

## TC1302B-AFVUA
designator U?
Low Quiescent Current Dual Output LDO, 8-Pin MSOP, Extended Temperature
footprint MSOP-UA8_N (TSOP, 8-Leads, Body 3x3mm, Pitch 0.65mm, IPC Medium Density)
footprint MSOP-UA8_L (TSOP, 8-Leads, Body 3x3mm, Pitch 0.65mm, IPC High Density)
footprint MSOP-UA8_M (TSOP, 8-Leads, Body 3x3mm, Pitch 0.65mm, IPC Low Density)
pins: 1 NC, 2 VOUT1 (power), 3 GND (power), 4 BYPASS, 5 ~{SHDN2} (in), 6 VOUT2 (power), 7 VIN (power), 8 ~{SHDN1} (in)

## TC1302B-AFVUATR
designator U?
Low Quiescent Current Dual Output LDO, 8-Pin MSOP, Extended Temperature, Tape and Reel
footprint MSOP-UA8_N (TSOP, 8-Leads, Body 3x3mm, Pitch 0.65mm, IPC Medium Density)
footprint MSOP-UA8_L (TSOP, 8-Leads, Body 3x3mm, Pitch 0.65mm, IPC High Density)
footprint MSOP-UA8_M (TSOP, 8-Leads, Body 3x3mm, Pitch 0.65mm, IPC Low Density)
pins: 1 NC, 2 VOUT1 (power), 3 GND (power), 4 BYPASS, 5 ~{SHDN2} (in), 6 VOUT2 (power), 7 VIN (power), 8 ~{SHDN1} (in)

## TC1302B-APVUA
designator U?
Low Quiescent Current Dual Output LDO, 8-Pin MSOP, Extended Temperature
footprint MSOP-UA8_N (TSOP, 8-Leads, Body 3x3mm, Pitch 0.65mm, IPC Medium Density)
footprint MSOP-UA8_L (TSOP, 8-Leads, Body 3x3mm, Pitch 0.65mm, IPC High Density)
footprint MSOP-UA8_M (TSOP, 8-Leads, Body 3x3mm, Pitch 0.65mm, IPC Low Density)
pins: 1 NC, 2 VOUT1 (power), 3 GND (power), 4 BYPASS, 5 ~{SHDN2} (in), 6 VOUT2 (power), 7 VIN (power), 8 ~{SHDN1} (in)

## TC1302B-APVUAR
designator U?
Low Quiescent Current Dual Output LDO, 8-Pin MSOP, Extended Temperature, Tape and Reel
footprint MSOP-UA8_N (TSOP, 8-Leads, Body 3x3mm, Pitch 0.65mm, IPC Medium Density)
footprint MSOP-UA8_L (TSOP, 8-Leads, Body 3x3mm, Pitch 0.65mm, IPC High Density)
footprint MSOP-UA8_M (TSOP, 8-Leads, Body 3x3mm, Pitch 0.65mm, IPC Low Density)
pins: 1 NC, 2 VOUT1 (power), 3 GND (power), 4 BYPASS, 5 ~{SHDN2} (in), 6 VOUT2 (power), 7 VIN (power), 8 ~{SHDN1} (in)

## TC1302B-DPVMF
designator U?
Low Quiescent Current Dual Output LDO, 8-Pin DFN, Extended Temperature
footprint DFN-MF8 (SON, 8-Leads, Body 3x3mm, Pitch 0.65mm, Microchip Recommended)
pins: 1 NC, 2 VOUT1 (power), 3 GND (power), 4 BYPASS, 5 ~{SHDN2} (in), 6 VOUT2 (power), 7 VIN (power), 8 ~{SHDN1} (in), 9 EP (power)

## TC1302B-DPVMFTR
designator U?
Low Quiescent Current Dual Output LDO, 8-Pin DFN, Extended Temperature, Tape and Reel
footprint DFN-MF8 (SON, 8-Leads, Body 3x3mm, Pitch 0.65mm, Microchip Recommended)
pins: 1 NC, 2 VOUT1 (power), 3 GND (power), 4 BYPASS, 5 ~{SHDN2} (in), 6 VOUT2 (power), 7 VIN (power), 8 ~{SHDN1} (in), 9 EP (power)

## TC1302B-DPVUA
designator U?
Low Quiescent Current Dual Output LDO, 8-Pin MSOP, Extended Temperature
footprint MSOP-UA8_N (TSOP, 8-Leads, Body 3x3mm, Pitch 0.65mm, IPC Medium Density)
footprint MSOP-UA8_L (TSOP, 8-Leads, Body 3x3mm, Pitch 0.65mm, IPC High Density)
footprint MSOP-UA8_M (TSOP, 8-Leads, Body 3x3mm, Pitch 0.65mm, IPC Low Density)
pins: 1 NC, 2 VOUT1 (power), 3 GND (power), 4 BYPASS, 5 ~{SHDN2} (in), 6 VOUT2 (power), 7 VIN (power), 8 ~{SHDN1} (in)

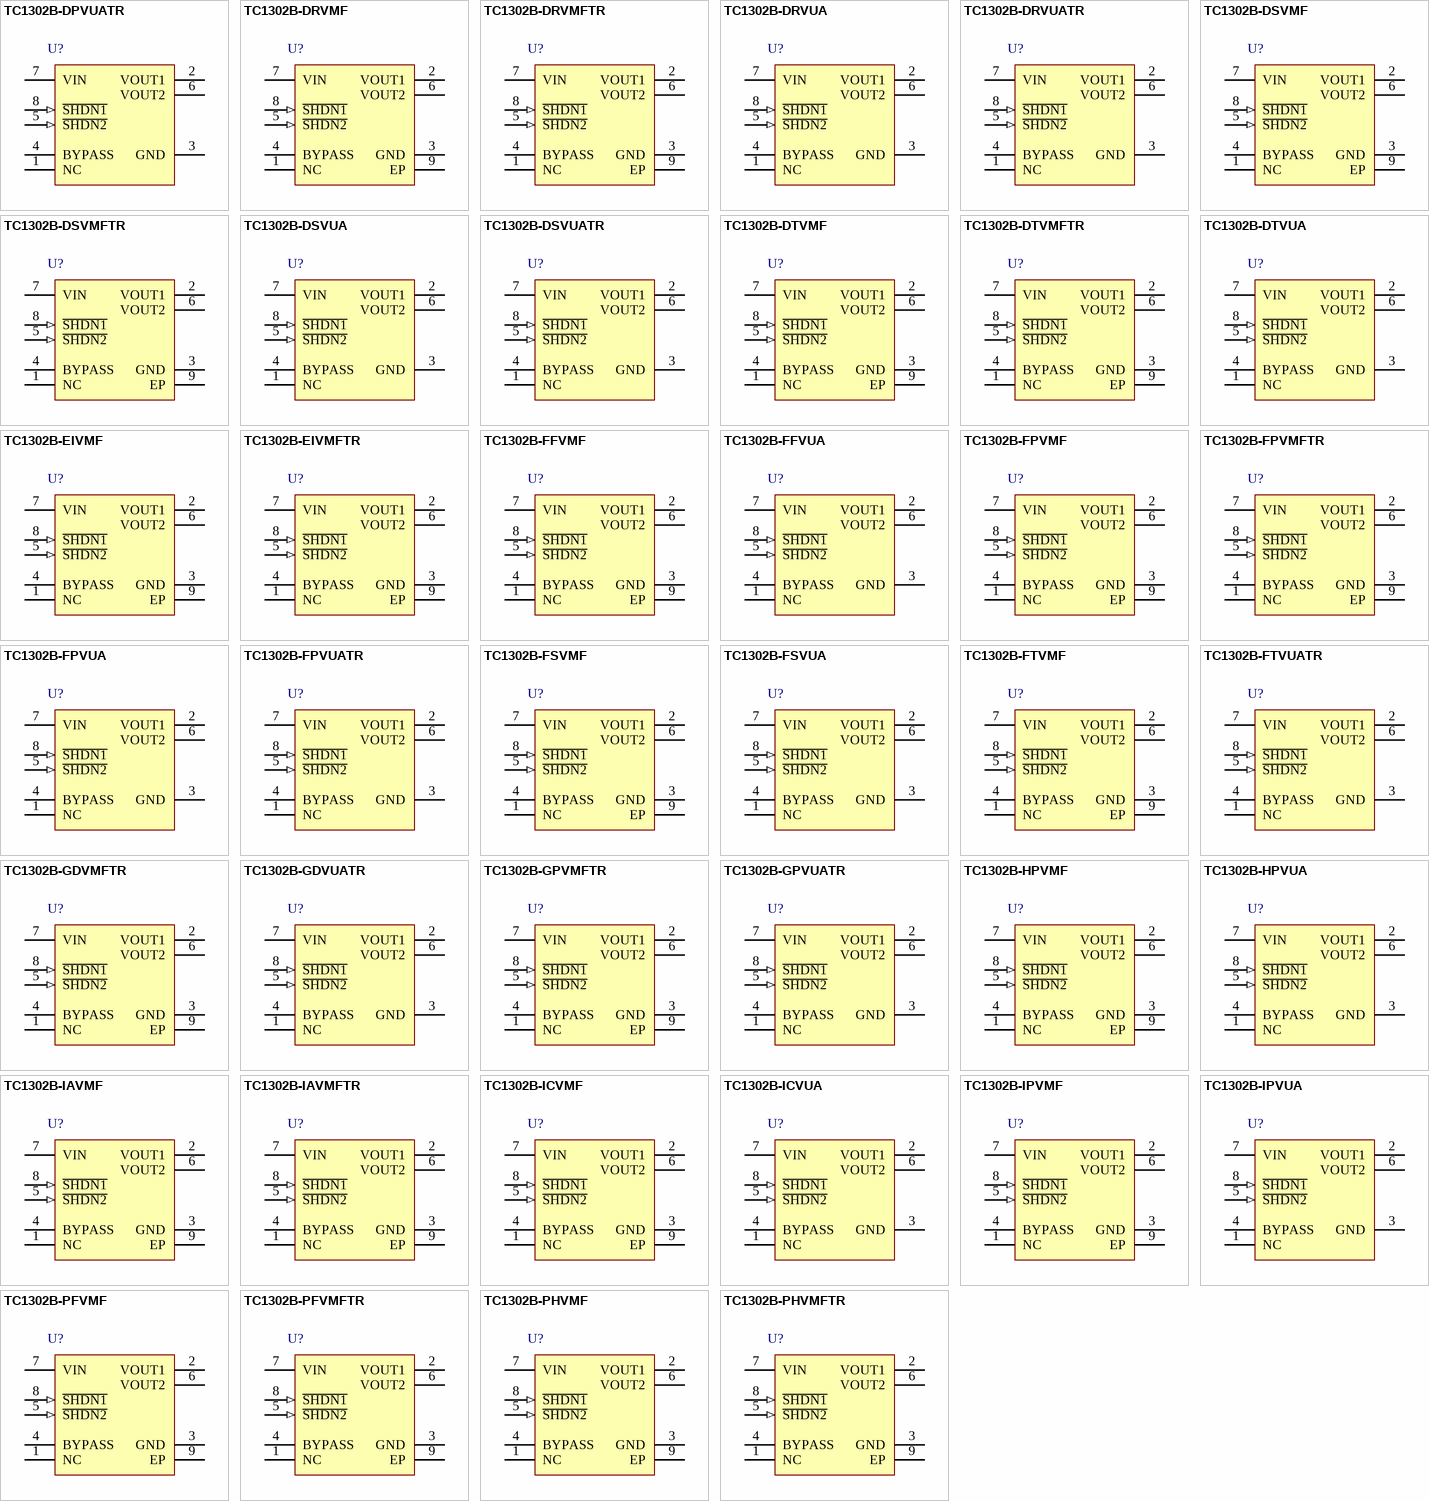
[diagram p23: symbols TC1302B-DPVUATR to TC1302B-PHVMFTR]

## TC1302B-DPVUATR
designator U?
Low Quiescent Current Dual Output LDO, 8-Pin MSOP, Extended Temperature, Tape and Reel
footprint MSOP-UA8_N (TSOP, 8-Leads, Body 3x3mm, Pitch 0.65mm, IPC Medium Density)
footprint MSOP-UA8_L (TSOP, 8-Leads, Body 3x3mm, Pitch 0.65mm, IPC High Density)
footprint MSOP-UA8_M (TSOP, 8-Leads, Body 3x3mm, Pitch 0.65mm, IPC Low Density)
pins: 1 NC, 2 VOUT1 (power), 3 GND (power), 4 BYPASS, 5 ~{SHDN2} (in), 6 VOUT2 (power), 7 VIN (power), 8 ~{SHDN1} (in)

## TC1302B-DRVMF
designator U?
Low Quiescent Current Dual Output LDO, 8-Pin DFN, Extended Temperature
footprint DFN-MF8 (SON, 8-Leads, Body 3x3mm, Pitch 0.65mm, Microchip Recommended)
pins: 1 NC, 2 VOUT1 (power), 3 GND (power), 4 BYPASS, 5 ~{SHDN2} (in), 6 VOUT2 (power), 7 VIN (power), 8 ~{SHDN1} (in), 9 EP (power)

## TC1302B-DRVMFTR
designator U?
Low Quiescent Current Dual Output LDO, 8-Pin DFN, Extended Temperature, Tape and Reel
footprint DFN-MF8 (SON, 8-Leads, Body 3x3mm, Pitch 0.65mm, Microchip Recommended)
pins: 1 NC, 2 VOUT1 (power), 3 GND (power), 4 BYPASS, 5 ~{SHDN2} (in), 6 VOUT2 (power), 7 VIN (power), 8 ~{SHDN1} (in), 9 EP (power)

## TC1302B-DRVUA
designator U?
Low Quiescent Current Dual Output LDO, 8-Pin MSOP, Extended Temperature
footprint MSOP-UA8_N (TSOP, 8-Leads, Body 3x3mm, Pitch 0.65mm, IPC Medium Density)
footprint MSOP-UA8_L (TSOP, 8-Leads, Body 3x3mm, Pitch 0.65mm, IPC High Density)
footprint MSOP-UA8_M (TSOP, 8-Leads, Body 3x3mm, Pitch 0.65mm, IPC Low Density)
pins: 1 NC, 2 VOUT1 (power), 3 GND (power), 4 BYPASS, 5 ~{SHDN2} (in), 6 VOUT2 (power), 7 VIN (power), 8 ~{SHDN1} (in)

## TC1302B-DRVUATR
designator U?
Low Quiescent Current Dual Output LDO, 8-Pin MSOP, Extended Temperature, Tape and Reel
footprint MSOP-UA8_N (TSOP, 8-Leads, Body 3x3mm, Pitch 0.65mm, IPC Medium Density)
footprint MSOP-UA8_L (TSOP, 8-Leads, Body 3x3mm, Pitch 0.65mm, IPC High Density)
footprint MSOP-UA8_M (TSOP, 8-Leads, Body 3x3mm, Pitch 0.65mm, IPC Low Density)
pins: 1 NC, 2 VOUT1 (power), 3 GND (power), 4 BYPASS, 5 ~{SHDN2} (in), 6 VOUT2 (power), 7 VIN (power), 8 ~{SHDN1} (in)

## TC1302B-DSVMF
designator U?
Low Quiescent Current Dual Output LDO, 8-Pin DFN, Extended Temperature
footprint DFN-MF8 (SON, 8-Leads, Body 3x3mm, Pitch 0.65mm, Microchip Recommended)
pins: 1 NC, 2 VOUT1 (power), 3 GND (power), 4 BYPASS, 5 ~{SHDN2} (in), 6 VOUT2 (power), 7 VIN (power), 8 ~{SHDN1} (in), 9 EP (power)

## TC1302B-DSVMFTR
designator U?
Low Quiescent Current Dual Output LDO, 8-Pin DFN, Extended Temperature, Tape and Reel
footprint DFN-MF8 (SON, 8-Leads, Body 3x3mm, Pitch 0.65mm, Microchip Recommended)
pins: 1 NC, 2 VOUT1 (power), 3 GND (power), 4 BYPASS, 5 ~{SHDN2} (in), 6 VOUT2 (power), 7 VIN (power), 8 ~{SHDN1} (in), 9 EP (power)

## TC1302B-DSVUA
designator U?
Low Quiescent Current Dual Output LDO, 8-Pin MSOP, Extended Temperature
footprint MSOP-UA8_N (TSOP, 8-Leads, Body 3x3mm, Pitch 0.65mm, IPC Medium Density)
footprint MSOP-UA8_L (TSOP, 8-Leads, Body 3x3mm, Pitch 0.65mm, IPC High Density)
footprint MSOP-UA8_M (TSOP, 8-Leads, Body 3x3mm, Pitch 0.65mm, IPC Low Density)
pins: 1 NC, 2 VOUT1 (power), 3 GND (power), 4 BYPASS, 5 ~{SHDN2} (in), 6 VOUT2 (power), 7 VIN (power), 8 ~{SHDN1} (in)

## TC1302B-DSVUATR
designator U?
Low Quiescent Current Dual Output LDO, 8-Pin MSOP, Extended Temperature, Tape and Reel
footprint MSOP-UA8_N (TSOP, 8-Leads, Body 3x3mm, Pitch 0.65mm, IPC Medium Density)
footprint MSOP-UA8_L (TSOP, 8-Leads, Body 3x3mm, Pitch 0.65mm, IPC High Density)
footprint MSOP-UA8_M (TSOP, 8-Leads, Body 3x3mm, Pitch 0.65mm, IPC Low Density)
pins: 1 NC, 2 VOUT1 (power), 3 GND (power), 4 BYPASS, 5 ~{SHDN2} (in), 6 VOUT2 (power), 7 VIN (power), 8 ~{SHDN1} (in)

## TC1302B-DTVMF
designator U?
Low Quiescent Current Dual Output LDO, 8-Pin DFN, Extended Temperature
footprint DFN-MF8 (SON, 8-Leads, Body 3x3mm, Pitch 0.65mm, Microchip Recommended)
pins: 1 NC, 2 VOUT1 (power), 3 GND (power), 4 BYPASS, 5 ~{SHDN2} (in), 6 VOUT2 (power), 7 VIN (power), 8 ~{SHDN1} (in), 9 EP (power)

## TC1302B-DTVMFTR
designator U?
Low Quiescent Current Dual Output LDO, 8-Pin DFN, Extended Temperature, Tape and Reel
footprint DFN-MF8 (SON, 8-Leads, Body 3x3mm, Pitch 0.65mm, Microchip Recommended)
pins: 1 NC, 2 VOUT1 (power), 3 GND (power), 4 BYPASS, 5 ~{SHDN2} (in), 6 VOUT2 (power), 7 VIN (power), 8 ~{SHDN1} (in), 9 EP (power)

## TC1302B-DTVUA
designator U?
Low Quiescent Current Dual Output LDO, 8-Pin MSOP, Extended Temperature
footprint MSOP-UA8_N (TSOP, 8-Leads, Body 3x3mm, Pitch 0.65mm, IPC Medium Density)
footprint MSOP-UA8_L (TSOP, 8-Leads, Body 3x3mm, Pitch 0.65mm, IPC High Density)
footprint MSOP-UA8_M (TSOP, 8-Leads, Body 3x3mm, Pitch 0.65mm, IPC Low Density)
pins: 1 NC, 2 VOUT1 (power), 3 GND (power), 4 BYPASS, 5 ~{SHDN2} (in), 6 VOUT2 (power), 7 VIN (power), 8 ~{SHDN1} (in)

## TC1302B-EIVMF
designator U?
Low Quiescent Current Dual Output LDO, 8-Pin DFN, Extended Temperature
footprint DFN-MF8 (SON, 8-Leads, Body 3x3mm, Pitch 0.65mm, Microchip Recommended)
pins: 1 NC, 2 VOUT1 (power), 3 GND (power), 4 BYPASS, 5 ~{SHDN2} (in), 6 VOUT2 (power), 7 VIN (power), 8 ~{SHDN1} (in), 9 EP (power)

## TC1302B-EIVMFTR
designator U?
Low Quiescent Current Dual Output LDO, 8-Pin DFN, Extended Temperature, Tape and Reel
footprint DFN-MF8 (SON, 8-Leads, Body 3x3mm, Pitch 0.65mm, Microchip Recommended)
pins: 1 NC, 2 VOUT1 (power), 3 GND (power), 4 BYPASS, 5 ~{SHDN2} (in), 6 VOUT2 (power), 7 VIN (power), 8 ~{SHDN1} (in), 9 EP (power)

## TC1302B-FFVMF
designator U?
Low Quiescent Current Dual Output LDO, 8-Pin DFN, Extended Temperature
footprint DFN-MF8 (SON, 8-Leads, Body 3x3mm, Pitch 0.65mm, Microchip Recommended)
pins: 1 NC, 2 VOUT1 (power), 3 GND (power), 4 BYPASS, 5 ~{SHDN2} (in), 6 VOUT2 (power), 7 VIN (power), 8 ~{SHDN1} (in), 9 EP (power)

## TC1302B-FFVUA
designator U?
Low Quiescent Current Dual Output LDO, 8-Pin MSOP, Extended Temperature
footprint MSOP-UA8_N (TSOP, 8-Leads, Body 3x3mm, Pitch 0.65mm, IPC Medium Density)
footprint MSOP-UA8_L (TSOP, 8-Leads, Body 3x3mm, Pitch 0.65mm, IPC High Density)
footprint MSOP-UA8_M (TSOP, 8-Leads, Body 3x3mm, Pitch 0.65mm, IPC Low Density)
pins: 1 NC, 2 VOUT1 (power), 3 GND (power), 4 BYPASS, 5 ~{SHDN2} (in), 6 VOUT2 (power), 7 VIN (power), 8 ~{SHDN1} (in)

## TC1302B-FPVMF
designator U?
Low Quiescent Current Dual Output LDO, 8-Pin DFN, Extended Temperature
footprint DFN-MF8 (SON, 8-Leads, Body 3x3mm, Pitch 0.65mm, Microchip Recommended)
pins: 1 NC, 2 VOUT1 (power), 3 GND (power), 4 BYPASS, 5 ~{SHDN2} (in), 6 VOUT2 (power), 7 VIN (power), 8 ~{SHDN1} (in), 9 EP (power)

## TC1302B-FPVMFTR
designator U?
Low Quiescent Current Dual Output LDO, 8-Pin DFN, Extended Temperature, Tape and Reel
footprint DFN-MF8 (SON, 8-Leads, Body 3x3mm, Pitch 0.65mm, Microchip Recommended)
pins: 1 NC, 2 VOUT1 (power), 3 GND (power), 4 BYPASS, 5 ~{SHDN2} (in), 6 VOUT2 (power), 7 VIN (power), 8 ~{SHDN1} (in), 9 EP (power)

## TC1302B-FPVUA
designator U?
Low Quiescent Current Dual Output LDO, 8-Pin MSOP, Extended Temperature
footprint MSOP-UA8_N (TSOP, 8-Leads, Body 3x3mm, Pitch 0.65mm, IPC Medium Density)
footprint MSOP-UA8_L (TSOP, 8-Leads, Body 3x3mm, Pitch 0.65mm, IPC High Density)
footprint MSOP-UA8_M (TSOP, 8-Leads, Body 3x3mm, Pitch 0.65mm, IPC Low Density)
pins: 1 NC, 2 VOUT1 (power), 3 GND (power), 4 BYPASS, 5 ~{SHDN2} (in), 6 VOUT2 (power), 7 VIN (power), 8 ~{SHDN1} (in)

## TC1302B-FPVUATR
designator U?
Low Quiescent Current Dual Output LDO, 8-Pin MSOP, Extended Temperature, Tape and Reel
footprint MSOP-UA8_N (TSOP, 8-Leads, Body 3x3mm, Pitch 0.65mm, IPC Medium Density)
footprint MSOP-UA8_L (TSOP, 8-Leads, Body 3x3mm, Pitch 0.65mm, IPC High Density)
footprint MSOP-UA8_M (TSOP, 8-Leads, Body 3x3mm, Pitch 0.65mm, IPC Low Density)
pins: 1 NC, 2 VOUT1 (power), 3 GND (power), 4 BYPASS, 5 ~{SHDN2} (in), 6 VOUT2 (power), 7 VIN (power), 8 ~{SHDN1} (in)

## TC1302B-FSVMF
designator U?
Low Quiescent Current Dual Output LDO, 8-Pin DFN, Extended Temperature
footprint DFN-MF8 (SON, 8-Leads, Body 3x3mm, Pitch 0.65mm, Microchip Recommended)
pins: 1 NC, 2 VOUT1 (power), 3 GND (power), 4 BYPASS, 5 ~{SHDN2} (in), 6 VOUT2 (power), 7 VIN (power), 8 ~{SHDN1} (in), 9 EP (power)

## TC1302B-FSVUA
designator U?
Low Quiescent Current Dual Output LDO, 8-Pin MSOP, Extended Temperature
footprint MSOP-UA8_N (TSOP, 8-Leads, Body 3x3mm, Pitch 0.65mm, IPC Medium Density)
footprint MSOP-UA8_L (TSOP, 8-Leads, Body 3x3mm, Pitch 0.65mm, IPC High Density)
footprint MSOP-UA8_M (TSOP, 8-Leads, Body 3x3mm, Pitch 0.65mm, IPC Low Density)
pins: 1 NC, 2 VOUT1 (power), 3 GND (power), 4 BYPASS, 5 ~{SHDN2} (in), 6 VOUT2 (power), 7 VIN (power), 8 ~{SHDN1} (in)

## TC1302B-FTVMF
designator U?
Low Quiescent Current Dual Output LDO, 8-Pin DFN, Extended Temperature
footprint DFN-MF8 (SON, 8-Leads, Body 3x3mm, Pitch 0.65mm, Microchip Recommended)
pins: 1 NC, 2 VOUT1 (power), 3 GND (power), 4 BYPASS, 5 ~{SHDN2} (in), 6 VOUT2 (power), 7 VIN (power), 8 ~{SHDN1} (in), 9 EP (power)

## TC1302B-FTVUATR
designator U?
Low Quiescent Current Dual Output LDO, 8-Pin MSOP, Extended Temperature, Tape and Reel
footprint MSOP-UA8_N (TSOP, 8-Leads, Body 3x3mm, Pitch 0.65mm, IPC Medium Density)
footprint MSOP-UA8_L (TSOP, 8-Leads, Body 3x3mm, Pitch 0.65mm, IPC High Density)
footprint MSOP-UA8_M (TSOP, 8-Leads, Body 3x3mm, Pitch 0.65mm, IPC Low Density)
pins: 1 NC, 2 VOUT1 (power), 3 GND (power), 4 BYPASS, 5 ~{SHDN2} (in), 6 VOUT2 (power), 7 VIN (power), 8 ~{SHDN1} (in)

## TC1302B-GDVMFTR
designator U?
Low Quiescent Current Dual Output LDO, 8-Pin DFN, Extended Temperature, Tape and Reel
footprint DFN-MF8 (SON, 8-Leads, Body 3x3mm, Pitch 0.65mm, Microchip Recommended)
pins: 1 NC, 2 VOUT1 (power), 3 GND (power), 4 BYPASS, 5 ~{SHDN2} (in), 6 VOUT2 (power), 7 VIN (power), 8 ~{SHDN1} (in), 9 EP (power)

## TC1302B-GDVUATR
designator U?
Low Quiescent Current Dual Output LDO, 8-Pin MSOP, Extended Temperature, Tape and Reel
footprint MSOP-UA8_N (TSOP, 8-Leads, Body 3x3mm, Pitch 0.65mm, IPC Medium Density)
footprint MSOP-UA8_L (TSOP, 8-Leads, Body 3x3mm, Pitch 0.65mm, IPC High Density)
footprint MSOP-UA8_M (TSOP, 8-Leads, Body 3x3mm, Pitch 0.65mm, IPC Low Density)
pins: 1 NC, 2 VOUT1 (power), 3 GND (power), 4 BYPASS, 5 ~{SHDN2} (in), 6 VOUT2 (power), 7 VIN (power), 8 ~{SHDN1} (in)

## TC1302B-GPVMFTR
designator U?
Low Quiescent Current Dual Output LDO, 8-Pin DFN, Extended Temperature, Tape and Reel
footprint DFN-MF8 (SON, 8-Leads, Body 3x3mm, Pitch 0.65mm, Microchip Recommended)
pins: 1 NC, 2 VOUT1 (power), 3 GND (power), 4 BYPASS, 5 ~{SHDN2} (in), 6 VOUT2 (power), 7 VIN (power), 8 ~{SHDN1} (in), 9 EP (power)

## TC1302B-GPVUATR
designator U?
Low Quiescent Current Dual Output LDO, 8-Pin MSOP, Extended Temperature, Tape and Reel
footprint MSOP-UA8_N (TSOP, 8-Leads, Body 3x3mm, Pitch 0.65mm, IPC Medium Density)
footprint MSOP-UA8_L (TSOP, 8-Leads, Body 3x3mm, Pitch 0.65mm, IPC High Density)
footprint MSOP-UA8_M (TSOP, 8-Leads, Body 3x3mm, Pitch 0.65mm, IPC Low Density)
pins: 1 NC, 2 VOUT1 (power), 3 GND (power), 4 BYPASS, 5 ~{SHDN2} (in), 6 VOUT2 (power), 7 VIN (power), 8 ~{SHDN1} (in)

## TC1302B-HPVMF
designator U?
Low Quiescent Current Dual Output LDO, 8-Pin DFN, Extended Temperature
footprint DFN-MF8 (SON, 8-Leads, Body 3x3mm, Pitch 0.65mm, Microchip Recommended)
pins: 1 NC, 2 VOUT1 (power), 3 GND (power), 4 BYPASS, 5 ~{SHDN2} (in), 6 VOUT2 (power), 7 VIN (power), 8 ~{SHDN1} (in), 9 EP (power)

## TC1302B-HPVUA
designator U?
Low Quiescent Current Dual Output LDO, 8-Pin MSOP, Extended Temperature
footprint MSOP-UA8_N (TSOP, 8-Leads, Body 3x3mm, Pitch 0.65mm, IPC Medium Density)
footprint MSOP-UA8_L (TSOP, 8-Leads, Body 3x3mm, Pitch 0.65mm, IPC High Density)
footprint MSOP-UA8_M (TSOP, 8-Leads, Body 3x3mm, Pitch 0.65mm, IPC Low Density)
pins: 1 NC, 2 VOUT1 (power), 3 GND (power), 4 BYPASS, 5 ~{SHDN2} (in), 6 VOUT2 (power), 7 VIN (power), 8 ~{SHDN1} (in)

## TC1302B-IAVMF
designator U?
Low Quiescent Current Dual Output LDO, 8-Pin DFN, Extended Temperature
footprint DFN-MF8 (SON, 8-Leads, Body 3x3mm, Pitch 0.65mm, Microchip Recommended)
pins: 1 NC, 2 VOUT1 (power), 3 GND (power), 4 BYPASS, 5 ~{SHDN2} (in), 6 VOUT2 (power), 7 VIN (power), 8 ~{SHDN1} (in), 9 EP (power)

## TC1302B-IAVMFTR
designator U?
Low Quiescent Current Dual Output LDO, 8-Pin DFN, Extended Temperature, Tape and Reel
footprint DFN-MF8 (SON, 8-Leads, Body 3x3mm, Pitch 0.65mm, Microchip Recommended)
pins: 1 NC, 2 VOUT1 (power), 3 GND (power), 4 BYPASS, 5 ~{SHDN2} (in), 6 VOUT2 (power), 7 VIN (power), 8 ~{SHDN1} (in), 9 EP (power)

## TC1302B-ICVMF
designator U?
Low Quiescent Current Dual Output LDO, 8-Pin DFN, Extended Temperature
footprint DFN-MF8 (SON, 8-Leads, Body 3x3mm, Pitch 0.65mm, Microchip Recommended)
pins: 1 NC, 2 VOUT1 (power), 3 GND (power), 4 BYPASS, 5 ~{SHDN2} (in), 6 VOUT2 (power), 7 VIN (power), 8 ~{SHDN1} (in), 9 EP (power)

## TC1302B-ICVUA
designator U?
Low Quiescent Current Dual Output LDO, 8-Pin MSOP, Extended Temperature
footprint MSOP-UA8_N (TSOP, 8-Leads, Body 3x3mm, Pitch 0.65mm, IPC Medium Density)
footprint MSOP-UA8_L (TSOP, 8-Leads, Body 3x3mm, Pitch 0.65mm, IPC High Density)
footprint MSOP-UA8_M (TSOP, 8-Leads, Body 3x3mm, Pitch 0.65mm, IPC Low Density)
pins: 1 NC, 2 VOUT1 (power), 3 GND (power), 4 BYPASS, 5 ~{SHDN2} (in), 6 VOUT2 (power), 7 VIN (power), 8 ~{SHDN1} (in)

## TC1302B-IPVMF
designator U?
Low Quiescent Current Dual Output LDO, 8-Pin DFN, Extended Temperature
footprint DFN-MF8 (SON, 8-Leads, Body 3x3mm, Pitch 0.65mm, Microchip Recommended)
pins: 1 NC, 2 VOUT1 (power), 3 GND (power), 4 BYPASS, 5 ~{SHDN2} (in), 6 VOUT2 (power), 7 VIN (power), 8 ~{SHDN1} (in), 9 EP (power)

## TC1302B-IPVUA
designator U?
Low Quiescent Current Dual Output LDO, 8-Pin MSOP, Extended Temperature
footprint MSOP-UA8_N (TSOP, 8-Leads, Body 3x3mm, Pitch 0.65mm, IPC Medium Density)
footprint MSOP-UA8_L (TSOP, 8-Leads, Body 3x3mm, Pitch 0.65mm, IPC High Density)
footprint MSOP-UA8_M (TSOP, 8-Leads, Body 3x3mm, Pitch 0.65mm, IPC Low Density)
pins: 1 NC, 2 VOUT1 (power), 3 GND (power), 4 BYPASS, 5 ~{SHDN2} (in), 6 VOUT2 (power), 7 VIN (power), 8 ~{SHDN1} (in)

## TC1302B-PFVMF
designator U?
Low Quiescent Current Dual Output LDO, 8-Pin DFN, Extended Temperature
footprint DFN-MF8 (SON, 8-Leads, Body 3x3mm, Pitch 0.65mm, Microchip Recommended)
pins: 1 NC, 2 VOUT1 (power), 3 GND (power), 4 BYPASS, 5 ~{SHDN2} (in), 6 VOUT2 (power), 7 VIN (power), 8 ~{SHDN1} (in), 9 EP (power)

## TC1302B-PFVMFTR
designator U?
Low Quiescent Current Dual Output LDO, 8-Pin DFN, Extended Temperature, Tape and Reel
footprint DFN-MF8 (SON, 8-Leads, Body 3x3mm, Pitch 0.65mm, Microchip Recommended)
pins: 1 NC, 2 VOUT1 (power), 3 GND (power), 4 BYPASS, 5 ~{SHDN2} (in), 6 VOUT2 (power), 7 VIN (power), 8 ~{SHDN1} (in), 9 EP (power)

## TC1302B-PHVMF
designator U?
Low Quiescent Current Dual Output LDO, 8-Pin DFN, Extended Temperature
footprint DFN-MF8 (SON, 8-Leads, Body 3x3mm, Pitch 0.65mm, Microchip Recommended)
pins: 1 NC, 2 VOUT1 (power), 3 GND (power), 4 BYPASS, 5 ~{SHDN2} (in), 6 VOUT2 (power), 7 VIN (power), 8 ~{SHDN1} (in), 9 EP (power)

## TC1302B-PHVMFTR
designator U?
Low Quiescent Current Dual Output LDO, 8-Pin DFN, Extended Temperature, Tape and Reel
footprint DFN-MF8 (SON, 8-Leads, Body 3x3mm, Pitch 0.65mm, Microchip Recommended)
pins: 1 NC, 2 VOUT1 (power), 3 GND (power), 4 BYPASS, 5 ~{SHDN2} (in), 6 VOUT2 (power), 7 VIN (power), 8 ~{SHDN1} (in), 9 EP (power)

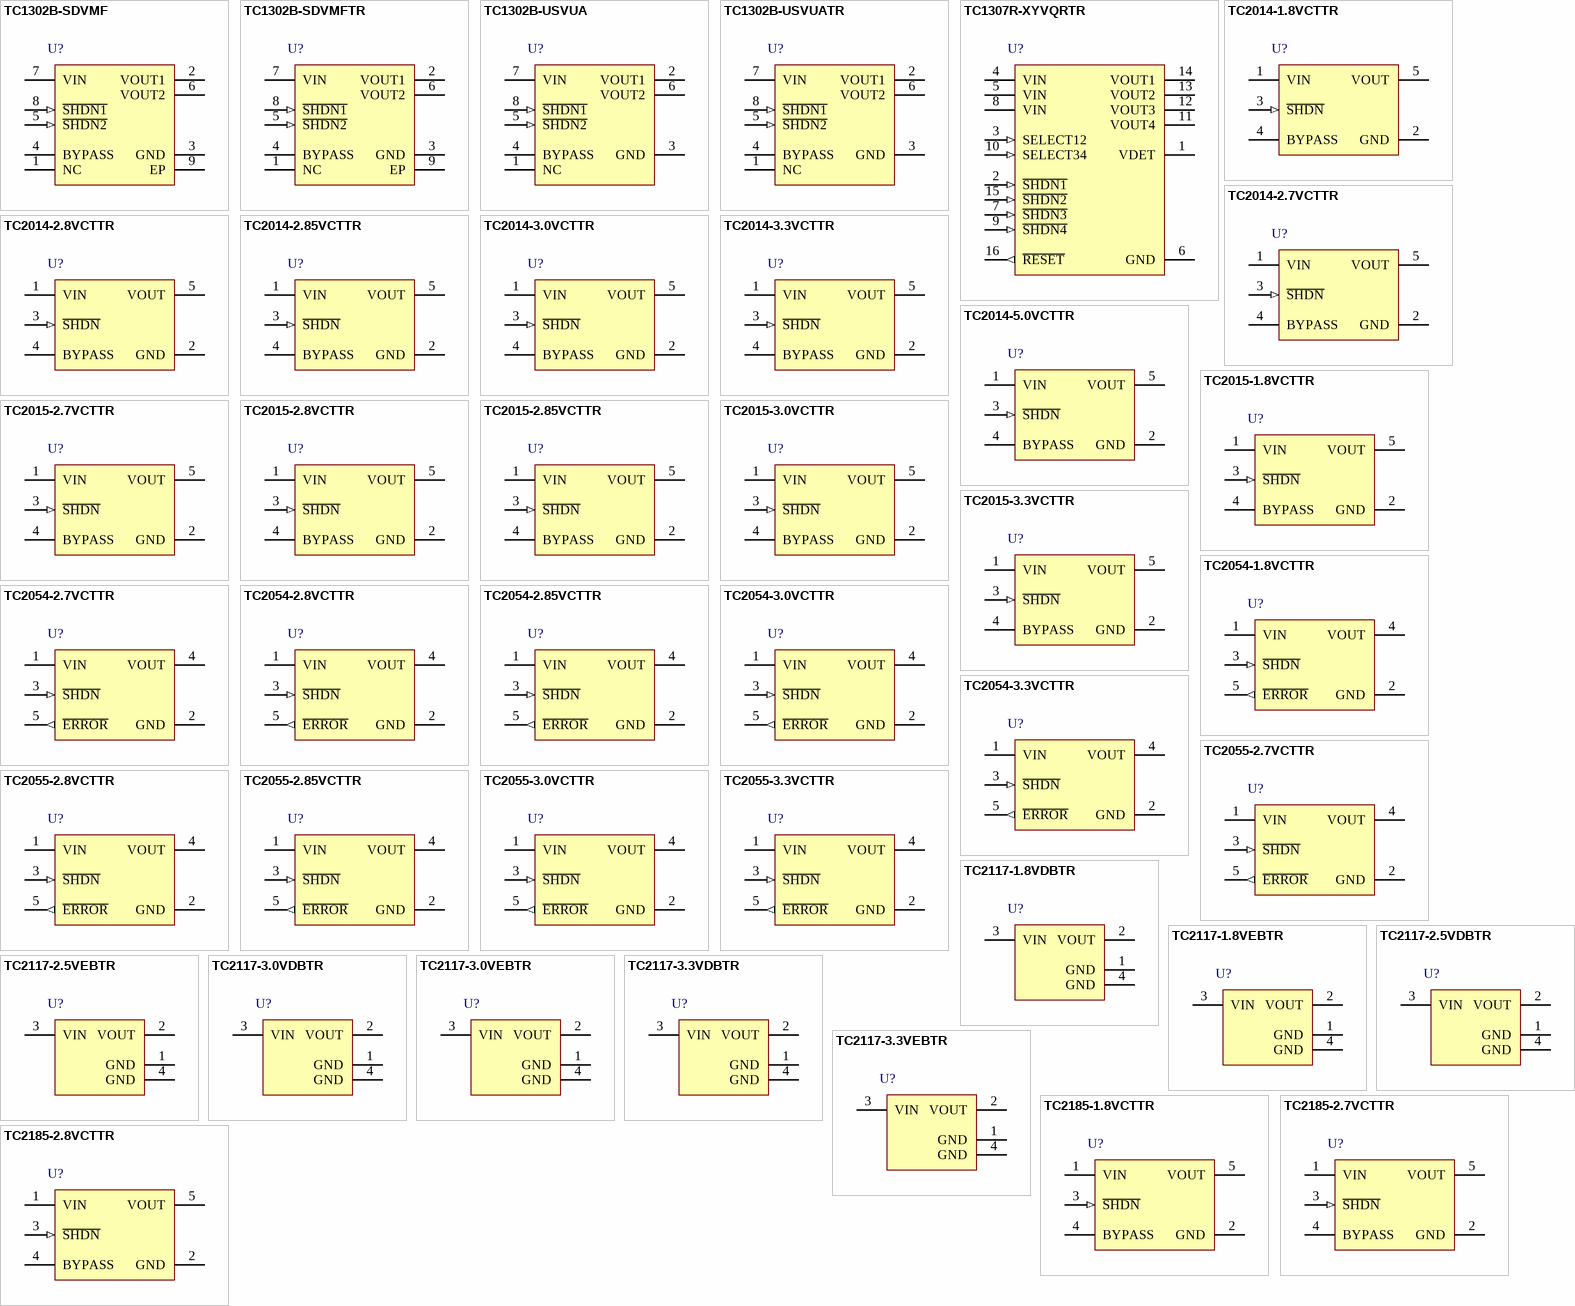
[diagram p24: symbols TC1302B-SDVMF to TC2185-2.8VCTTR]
